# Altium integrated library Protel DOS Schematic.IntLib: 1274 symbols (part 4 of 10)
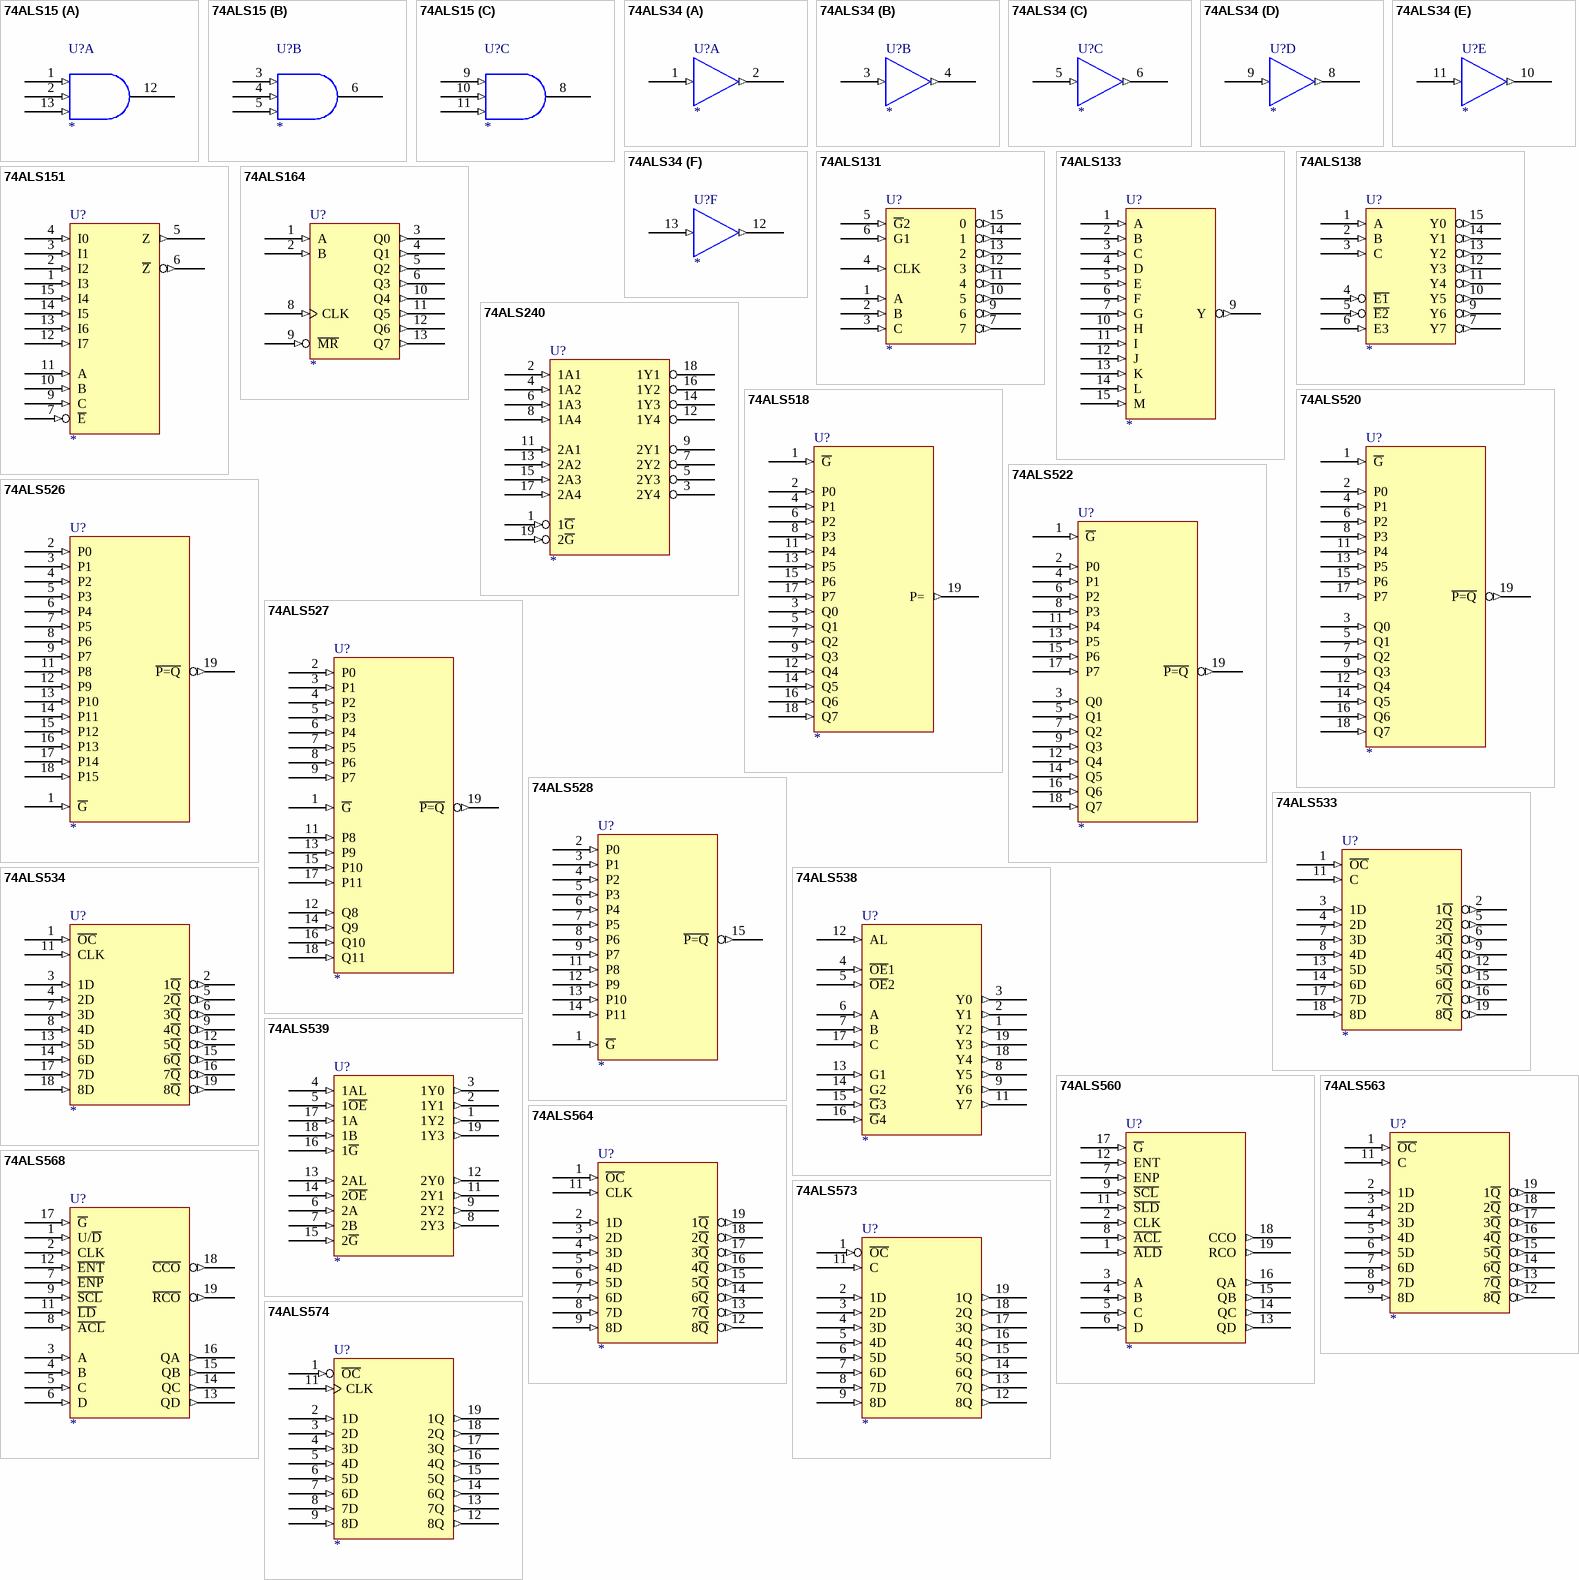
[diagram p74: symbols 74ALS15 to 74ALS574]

## 74ALS564
designator U?
footprint DIP-20
pins: 1 ~{OC} (in), 2 1D (in), 3 2D (in), 4 3D (in), 5 4D (in), 6 5D (in), 7 6D (in), 8 7D (in), 9 8D (in), 10 GND (power) hidden to GND, 11 CLK (in), 12 8~{Q} (out), 13 7~{Q} (out), 14 6~{Q} (out), 15 5~{Q} (out), 16 4~{Q} (out), 17 3~{Q} (out), 18 2~{Q} (out), 19 1~{Q} (out), 20 VCC (power) hidden to VCC
2 alternate drawings of the same symbol

## 74ALS568
designator U?
footprint DIP-20
pins: 1 U/~{D} (in), 2 CLK (in), 3 A (in), 4 B (in), 5 C (in), 6 D (in), 7 ~{ENP} (in), 8 ~{ACL} (in), 9 ~{SCL} (in), 10 GND (power) hidden to GND, 11 ~{LD} (in), 12 ~{ENT} (in), 13 QD (out), 14 QC (out), 15 QB (out), 16 QA (out), 17 ~{G} (in), 18 ~{CCO} (out), 19 ~{RCO} (out), 20 VCC (power) hidden to VCC
2 alternate drawings of the same symbol

## 74ALS573
designator U?
footprint DIP-20
footprint DIP20-O
pins: 1 ~{OC} (in), 2 1D (in), 3 2D (in), 4 3D (in), 5 4D (in), 6 5D (in), 7 6D (in), 8 7D (in), 9 8D (in), 10 GND (power) hidden to GND, 11 C (in), 12 8Q (out), 13 7Q (out), 14 6Q (out), 15 5Q (out), 16 4Q (out), 17 3Q (out), 18 2Q (out), 19 1Q (out), 20 VCC (power) hidden to VCC
2 alternate drawings of the same symbol

## 74ALS574
designator U?
footprint DIP-20
pins: 1 ~{OC} (in), 2 1D (in), 3 2D (in), 4 3D (in), 5 4D (in), 6 5D (in), 7 6D (in), 8 7D (in), 9 8D (in), 10 GND (power) hidden to GND, 11 CLK (in), 12 8Q (out), 13 7Q (out), 14 6Q (out), 15 5Q (out), 16 4Q (out), 17 3Q (out), 18 2Q (out), 19 1Q (out), 20 VCC (power) hidden to VCC
2 alternate drawings of the same symbol

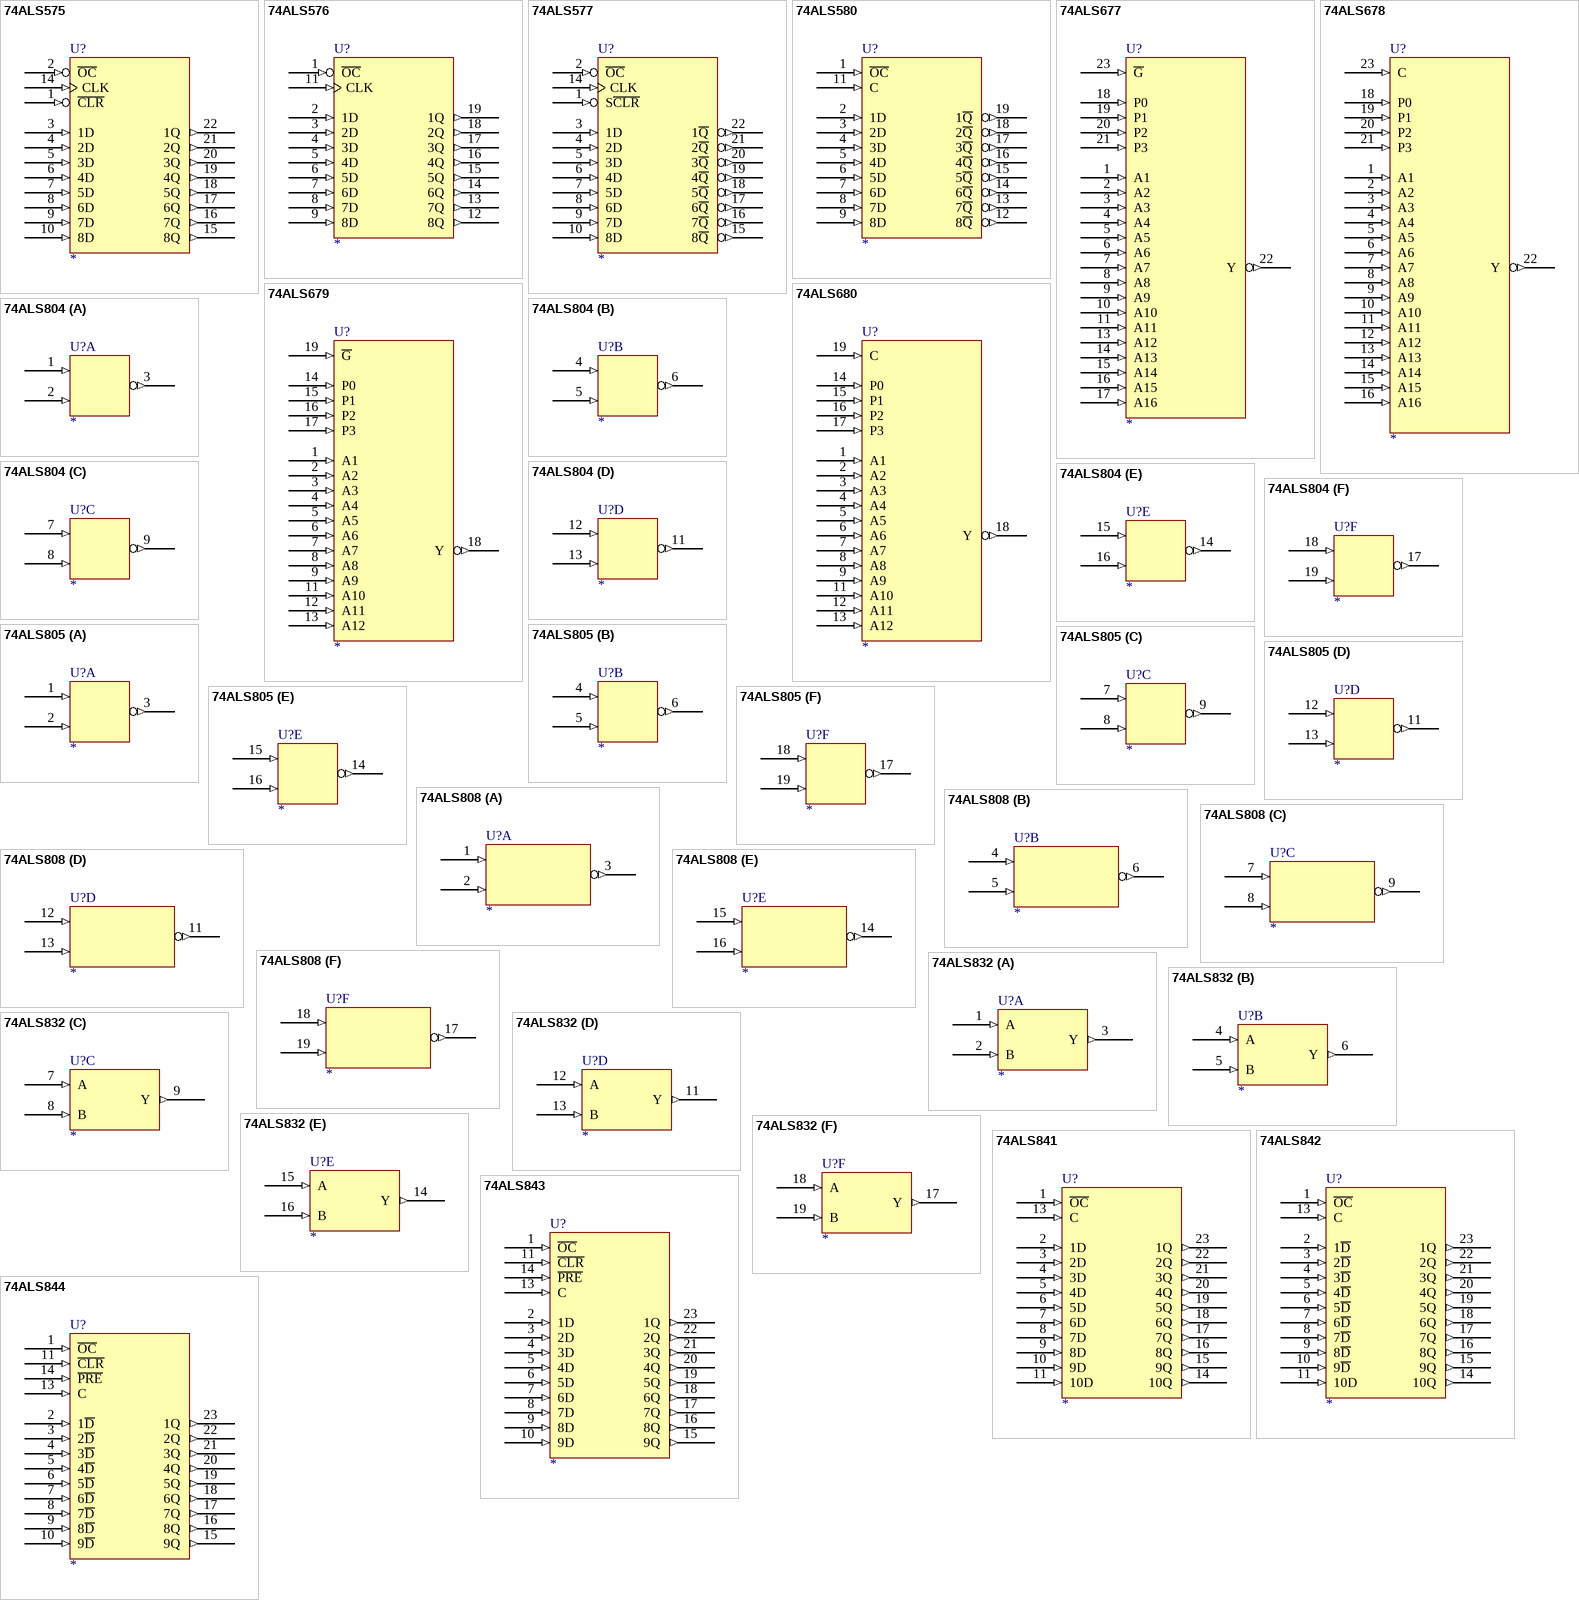
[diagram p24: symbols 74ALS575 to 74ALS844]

## 74ALS575
designator U?
footprint DIP-24
pins: 1 ~{CLR} (in), 2 ~{OC} (in), 3 1D (in), 4 2D (in), 5 3D (in), 6 4D (in), 7 5D (in), 8 6D (in), 9 7D (in), 10 8D (in), 12 GND (power) hidden to GND, 14 CLK (in), 15 8Q (out), 16 7Q (out), 17 6Q (out), 18 5Q (out), 19 4Q (out), 20 3Q (out), 21 2Q (out), 22 1Q (out), 24 VCC (power) hidden to VCC
2 alternate drawings of the same symbol

## 74ALS576
designator U?
footprint DIP-20
pins: 1 ~{OC} (in), 2 1D (in), 3 2D (in), 4 3D (in), 5 4D (in), 6 5D (in), 7 6D (in), 8 7D (in), 9 8D (in), 10 GND (power) hidden to GND, 11 CLK (in), 12 8Q (out), 13 7Q (out), 14 6Q (out), 15 5Q (out), 16 4Q (out), 17 3Q (out), 18 2Q (out), 19 1Q (out), 20 VCC (power) hidden to VCC
2 alternate drawings of the same symbol

## 74ALS577
designator U?
footprint DIP-24
pins: 1 S~{CLR} (in), 2 ~{OC} (in), 3 1D (in), 4 2D (in), 5 3D (in), 6 4D (in), 7 5D (in), 8 6D (in), 9 7D (in), 10 8D (in), 12 GND (power) hidden to GND, 14 CLK (in), 15 8~{Q} (out), 16 7~{Q} (out), 17 6~{Q} (out), 18 5~{Q} (out), 19 4~{Q} (out), 20 3~{Q} (out), 21 2~{Q} (out), 22 1~{Q} (out), 24 VCC (power) hidden to VCC
2 alternate drawings of the same symbol

## 74ALS580
designator U?
footprint DIP-20
pins: 1 ~{OC} (in), 2 1D (in), 3 2D (in), 4 3D (in), 5 4D (in), 6 5D (in), 7 6D (in), 8 7D (in), 9 8D (in), 10 GND (power) hidden to GND, 11 C (in), 12 8~{Q} (out), 13 7~{Q} (out), 14 6~{Q} (out), 15 5~{Q} (out), 16 4~{Q} (out), 17 3~{Q} (out), 18 2~{Q} (out), 19 1~{Q} (out), 20 VCC (power) hidden to VCC
2 alternate drawings of the same symbol

## 74ALS677
designator U?
footprint DIP-24
pins: 1 A1 (in), 2 A2 (in), 3 A3 (in), 4 A4 (in), 5 A5 (in), 6 A6 (in), 7 A7 (in), 8 A8 (in), 9 A9 (in), 10 A10 (in), 11 A11 (in), 12 GND (power) hidden to GND, 13 A12 (in), 14 A13 (in), 15 A14 (in), 16 A15 (in), 17 A16 (in), 18 P0 (in), 19 P1 (in), 20 P2 (in), 21 P3 (in), 22 Y (out), 23 ~{G} (in), 24 VCC (power) hidden to VCC
2 alternate drawings of the same symbol

## 74ALS678
designator U?
footprint DIP-24
pins: 1 A1 (in), 2 A2 (in), 3 A3 (in), 4 A4 (in), 5 A5 (in), 6 A6 (in), 7 A7 (in), 8 A8 (in), 9 A9 (in), 10 A10 (in), 11 A11 (in), 12 A12 (in), 12 GND (power) hidden to GND, 13 A13 (in), 14 A14 (in), 15 A15 (in), 16 A16 (in), 18 P0 (in), 19 P1 (in), 20 P2 (in), 21 P3 (in), 22 Y (out), 23 C (in), 24 VCC (power) hidden to VCC
2 alternate drawings of the same symbol

## 74ALS679
designator U?
footprint DIP-20
pins: 1 A1 (in), 2 A2 (in), 3 A3 (in), 4 A4 (in), 5 A5 (in), 6 A6 (in), 7 A7 (in), 8 A8 (in), 9 A9 (in), 10 GND (power) hidden to GND, 11 A10 (in), 12 A11 (in), 13 A12 (in), 14 P0 (in), 15 P1 (in), 16 P2 (in), 17 P3 (in), 18 Y (out), 19 ~{G} (in), 20 VCC (power) hidden to VCC
2 alternate drawings of the same symbol

## 74ALS680
designator U?
footprint DIP-20
pins: 1 A1 (in), 2 A2 (in), 3 A3 (in), 4 A4 (in), 5 A5 (in), 6 A6 (in), 7 A7 (in), 8 A8 (in), 9 A9 (in), 10 GND (power) hidden to GND, 11 A10 (in), 12 A11 (in), 13 A12 (in), 14 P0 (in), 15 P1 (in), 16 P2 (in), 17 P3 (in), 18 Y (out), 19 C (in), 20 VCC (power) hidden to VCC
2 alternate drawings of the same symbol

## 74ALS804
designator U?
footprint DIP-20
part A pins: 1 (in), 2 (in), 3 (out), 10 GND (power) hidden to GND, 20 VCC (power) hidden to VCC
part B pins: 4 (in), 5 (in), 6 (out), 10 GND (power) hidden to GND, 20 VCC (power) hidden to VCC
part C pins: 7 (in), 8 (in), 9 (out), 10 GND (power) hidden to GND, 20 VCC (power) hidden to VCC
part D pins: 10 GND (power) hidden to GND, 11 (out), 12 (in), 13 (in), 20 VCC (power) hidden to VCC
part E pins: 10 GND (power) hidden to GND, 14 (out), 15 (in), 16 (in), 20 VCC (power) hidden to VCC
part F pins: 10 GND (power) hidden to GND, 17 (out), 18 (in), 19 (in), 20 VCC (power) hidden to VCC
2 alternate drawings of the same symbol

## 74ALS805
designator U?
footprint DIP-20
part A pins: 1 (in), 2 (in), 3 (out), 10 GND (power) hidden to GND, 20 VCC (power) hidden to VCC
part B pins: 4 (in), 5 (in), 6 (out), 10 GND (power) hidden to GND, 20 VCC (power) hidden to VCC
part C pins: 7 (in), 8 (in), 9 (out), 10 GND (power) hidden to GND, 20 VCC (power) hidden to VCC
part D pins: 10 GND (power) hidden to GND, 11 (out), 12 (in), 13 (in), 20 VCC (power) hidden to VCC
part E pins: 10 GND (power) hidden to GND, 14 (out), 15 (in), 16 (in), 20 VCC (power) hidden to VCC
part F pins: 10 GND (power) hidden to GND, 17 (out), 18 (in), 19 (in), 20 VCC (power) hidden to VCC
2 alternate drawings of the same symbol

## 74ALS808
designator U?
footprint DIP-20
part A pins: 1 (in), 2 (in), 3 (out), 10 GND (power) hidden to GND, 20 VCC (power) hidden to VCC
part B pins: 4 (in), 5 (in), 6 (out), 10 GND (power) hidden to GND, 20 VCC (power) hidden to VCC
part C pins: 7 (in), 8 (in), 9 (out), 10 GND (power) hidden to GND, 20 VCC (power) hidden to VCC
part D pins: 10 GND (power) hidden to GND, 11 (out), 12 (in), 13 (in), 20 VCC (power) hidden to VCC
part E pins: 10 GND (power) hidden to GND, 14 (out), 15 (in), 16 (in), 20 VCC (power) hidden to VCC
part F pins: 10 GND (power) hidden to GND, 17 (out), 18 (in), 19 (in), 20 VCC (power) hidden to VCC
2 alternate drawings of the same symbol

## 74ALS832
designator U?
footprint DIP-20
part A pins: 1 A (in), 2 B (in), 3 Y (out), 10 GND (power) hidden to GND, 20 VCC (power) hidden to VCC
part B pins: 4 A (in), 5 B (in), 6 Y (out), 10 GND (power) hidden to GND, 20 VCC (power) hidden to VCC
part C pins: 7 A (in), 8 B (in), 9 Y (out), 10 GND (power) hidden to GND, 20 VCC (power) hidden to VCC
part D pins: 10 GND (power) hidden to GND, 11 Y (out), 12 A (in), 13 B (in), 20 VCC (power) hidden to VCC
part E pins: 10 GND (power) hidden to GND, 14 Y (out), 15 A (in), 16 B (in), 20 VCC (power) hidden to VCC
part F pins: 10 GND (power) hidden to GND, 17 Y (out), 18 A (in), 19 B (in), 20 VCC (power) hidden to VCC
2 alternate drawings of the same symbol

## 74ALS841
designator U?
footprint DIP-24
pins: 1 ~{OC} (in), 2 1D (in), 3 2D (in), 4 3D (in), 5 4D (in), 6 5D (in), 7 6D (in), 8 7D (in), 9 8D (in), 10 9D (in), 11 10D (in), 12 GND (power) hidden to GND, 13 C (in), 14 10Q (out), 15 9Q (out), 16 8Q (out), 17 7Q (out), 18 6Q (out), 19 5Q (out), 20 4Q (out), 21 3Q (out), 22 2Q (out), 23 1Q (out), 24 VCC (power) hidden to VCC
2 alternate drawings of the same symbol

## 74ALS842
designator U?
footprint DIP-24
pins: 1 ~{OC} (in), 2 1~{D} (in), 3 2~{D} (in), 4 3~{D} (in), 5 4~{D} (in), 6 5~{D} (in), 7 6~{D} (in), 8 7~{D} (in), 9 8~{D} (in), 10 9~{D} (in), 11 10D (in), 12 GND (power) hidden to GND, 13 C (in), 14 10Q (out), 15 9Q (out), 16 8Q (out), 17 7Q (out), 18 6Q (out), 19 5Q (out), 20 4Q (out), 21 3Q (out), 22 2Q (out), 23 1Q (out), 24 VCC (power) hidden to VCC
2 alternate drawings of the same symbol

## 74ALS843
designator U?
footprint DIP-24
pins: 1 ~{OC} (in), 2 1D (in), 3 2D (in), 4 3D (in), 5 4D (in), 6 5D (in), 7 6D (in), 8 7D (in), 9 8D (in), 10 9D (in), 11 ~{CLR} (in), 12 GND (power) hidden to GND, 13 C (in), 14 ~{PRE} (in), 15 9Q (out), 16 8Q (out), 17 7Q (out), 18 6Q (out), 19 5Q (out), 20 4Q (out), 21 3Q (out), 22 2Q (out), 23 1Q (out), 24 VCC (power) hidden to VCC
2 alternate drawings of the same symbol

## 74ALS844
designator U?
footprint DIP-24
pins: 1 ~{OC} (in), 2 1~{D} (in), 3 2~{D} (in), 4 3~{D} (in), 5 4~{D} (in), 6 5~{D} (in), 7 6~{D} (in), 8 7~{D} (in), 9 8~{D} (in), 10 9~{D} (in), 11 ~{CLR} (in), 12 GND (power) hidden to GND, 13 C (in), 14 ~{PRE} (in), 15 9Q (out), 16 8Q (out), 17 7Q (out), 18 6Q (out), 19 5Q (out), 20 4Q (out), 21 3Q (out), 22 2Q (out), 23 1Q (out), 24 VCC (power) hidden to VCC
2 alternate drawings of the same symbol

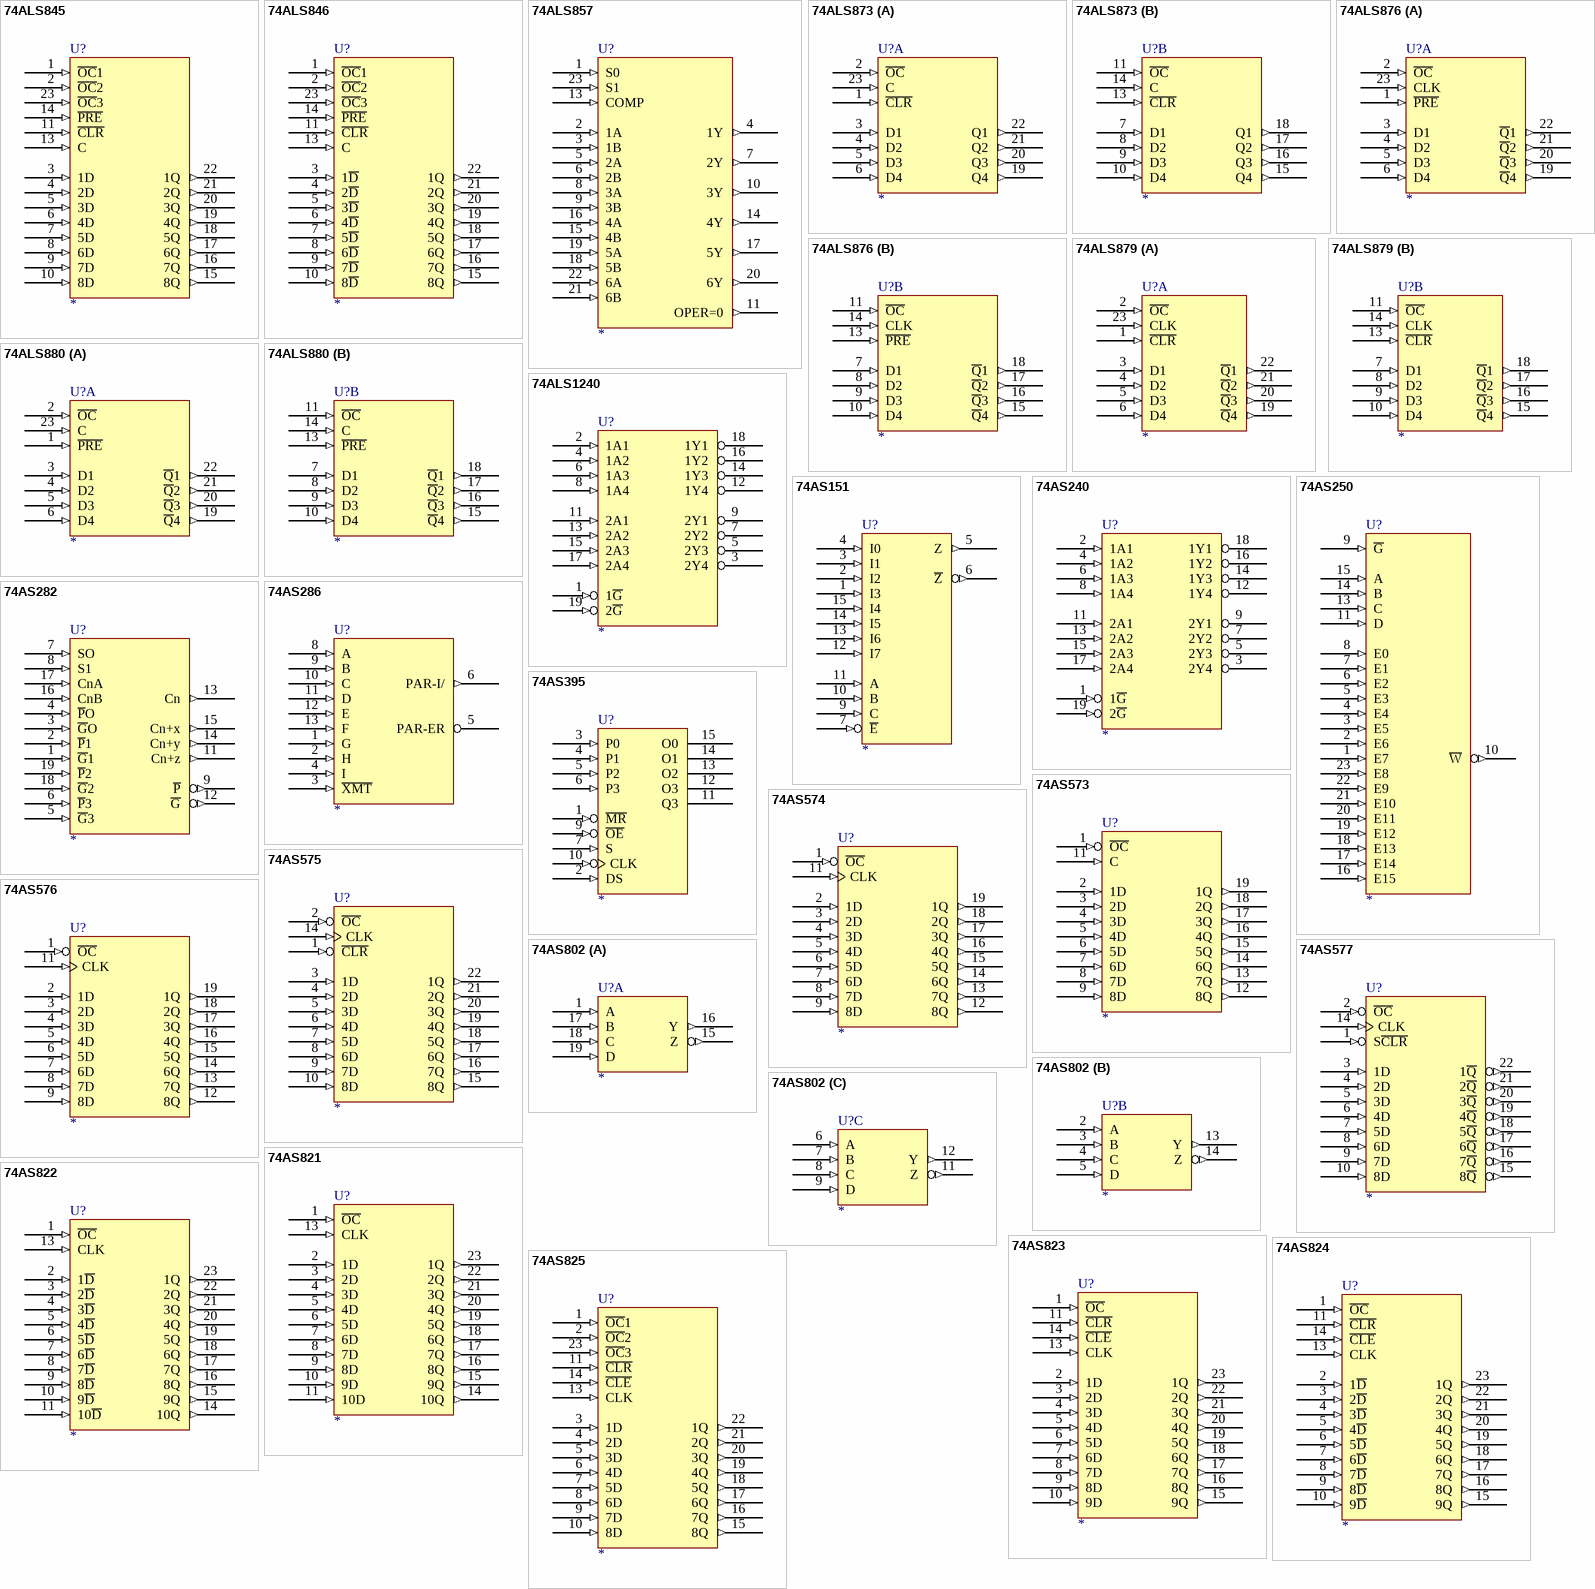
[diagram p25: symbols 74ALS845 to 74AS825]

## 74ALS845
designator U?
footprint DIP-24
pins: 1 ~{OC}1 (in), 2 ~{OC}2 (in), 3 1D (in), 4 2D (in), 5 3D (in), 6 4D (in), 7 5D (in), 8 6D (in), 9 7D (in), 10 8D (in), 11 ~{CLR} (in), 12 GND (power) hidden to GND, 13 C (in), 14 ~{PRE} (in), 15 8Q (out), 16 7Q (out), 17 6Q (out), 18 5Q (out), 19 4Q (out), 20 3Q (out), 21 2Q (out), 22 1Q (out), 23 ~{OC}3 (in), 24 VCC (power) hidden to VCC
2 alternate drawings of the same symbol

## 74ALS846
designator U?
footprint DIP-24
pins: 1 ~{OC}1 (in), 2 ~{OC}2 (in), 3 1~{D} (in), 4 2~{D} (in), 5 3~{D} (in), 6 4~{D} (in), 7 5~{D} (in), 8 6~{D} (in), 9 7~{D} (in), 10 8~{D} (in), 11 ~{CLR} (in), 12 GND (power) hidden to GND, 13 C (in), 14 ~{PRE} (in), 15 8Q (out), 16 7Q (out), 17 6Q (out), 18 5Q (out), 19 4Q (out), 20 3Q (out), 21 2Q (out), 22 1Q (out), 23 ~{OC}3 (in), 24 VCC (power) hidden to VCC
2 alternate drawings of the same symbol

## 74ALS857
designator U?
footprint DIP-24
pins: 1 S0 (in), 2 1A (in), 3 1B (in), 4 1Y (out), 5 2A (in), 6 2B (in), 7 2Y (out), 8 3A (in), 9 3B (in), 10 3Y (out), 11 OPER=0 (out), 12 GND (power) hidden to GND, 13 COMP (in), 14 4Y (out), 15 4B (in), 16 4A (in), 17 5Y (out), 18 5B (in), 19 5A (in), 20 6Y (out), 21 6B (in), 22 6A (in), 23 S1 (in), 24 VCC (power) hidden to VCC
2 alternate drawings of the same symbol

## 74ALS873
designator U?
footprint DIP-24
part A pins: 1 ~{CLR} (in), 2 ~{OC} (in), 3 D1 (in), 4 D2 (in), 5 D3 (in), 6 D4 (in), 12 GND (power) hidden to GND, 19 Q4 (out), 20 Q3 (out), 21 Q2 (out), 22 Q1 (out), 23 C (in), 24 VCC (power) hidden to VCC
part B pins: 7 D1 (in), 8 D2 (in), 9 D3 (in), 10 D4 (in), 11 ~{OC} (in), 12 GND (power) hidden to GND, 13 ~{CLR} (in), 14 C (in), 15 Q4 (out), 16 Q3 (out), 17 Q2 (out), 18 Q1 (out), 24 VCC (power) hidden to VCC
2 alternate drawings of the same symbol

## 74ALS876
designator U?
footprint DIP-24
part A pins: 1 ~{PRE} (in), 2 ~{OC} (in), 3 D1 (in), 4 D2 (in), 5 D3 (in), 6 D4 (in), 12 GND (power) hidden to GND, 19 ~{Q}4 (out), 20 ~{Q}3 (out), 21 ~{Q}2 (out), 22 ~{Q}1 (out), 23 CLK (in), 24 VCC (power) hidden to VCC
part B pins: 7 D1 (in), 8 D2 (in), 9 D3 (in), 10 D4 (in), 11 ~{OC} (in), 12 GND (power) hidden to GND, 13 ~{PRE} (in), 14 CLK (in), 15 ~{Q}4 (out), 16 ~{Q}3 (out), 17 ~{Q}2 (out), 18 ~{Q}1 (out), 24 VCC (power) hidden to VCC
2 alternate drawings of the same symbol

## 74ALS879
designator U?
footprint DIP-24
part A pins: 1 ~{CLR} (in), 2 ~{OC} (in), 3 D1 (in), 4 D2 (in), 5 D3 (in), 6 D4 (in), 12 GND (power) hidden to GND, 19 ~{Q}4 (out), 20 ~{Q}3 (out), 21 ~{Q}2 (out), 22 ~{Q}1 (out), 23 CLK (in), 24 VCC (power) hidden to VCC
part B pins: 7 D1 (in), 8 D2 (in), 9 D3 (in), 10 D4 (in), 11 ~{OC} (in), 12 GND (power) hidden to GND, 13 ~{CLR} (in), 14 CLK (in), 15 ~{Q}4 (out), 16 ~{Q}3 (out), 17 ~{Q}2 (out), 18 ~{Q}1 (out), 24 VCC (power) hidden to VCC
2 alternate drawings of the same symbol

## 74ALS880
designator U?
footprint DIP-24
part A pins: 1 ~{PRE} (in), 2 ~{OC} (in), 3 D1 (in), 4 D2 (in), 5 D3 (in), 6 D4 (in), 12 GND (power) hidden to GND, 19 ~{Q}4 (out), 20 ~{Q}3 (out), 21 ~{Q}2 (out), 22 ~{Q}1 (out), 23 C (in), 24 VCC (power) hidden to VCC
part B pins: 7 D1 (in), 8 D2 (in), 9 D3 (in), 10 D4 (in), 11 ~{OC} (in), 12 GND (power) hidden to GND, 13 ~{PRE} (in), 14 C (in), 15 ~{Q}4 (out), 16 ~{Q}3 (out), 17 ~{Q}2 (out), 18 ~{Q}1 (out), 24 VCC (power) hidden to VCC
2 alternate drawings of the same symbol

## 74ALS1240
designator U?
footprint DIP-20
pins: 1 1~{G} (in), 2 1A1 (in), 3 2Y4 (hiz), 4 1A2 (in), 5 2Y3 (hiz), 6 1A3 (in), 7 2Y2 (hiz), 8 1A4 (in), 9 2Y1 (hiz), 10 GND (power) hidden to GND, 11 2A1 (in), 12 1Y4 (hiz), 13 2A2 (in), 14 1Y3 (hiz), 15 2A3 (in), 16 1Y2 (hiz), 17 2A4 (in), 18 1Y1 (hiz), 19 2~{G} (in), 20 VCC (power) hidden to VCC
2 alternate drawings of the same symbol

## 74AS151
designator U?
footprint DIP-16
pins: 1 I3 (in), 2 I2 (in), 3 I1 (in), 4 I0 (in), 5 Z (out), 6 ~{Z} (out), 7 ~{E} (in), 8 GND (power) hidden to GND, 9 C (in), 10 B (in), 11 A (in), 12 I7 (in), 13 I6 (in), 14 I5 (in), 15 I4 (in), 16 VCC (power) hidden to VCC
2 alternate drawings of the same symbol

## 74AS240
designator U?
footprint DIP-20
pins: 1 1~{G} (in), 2 1A1 (in), 3 2Y4 (hiz), 4 1A2 (in), 5 2Y3 (hiz), 6 1A3 (in), 7 2Y2 (hiz), 8 1A4 (in), 9 2Y1 (hiz), 10 GND (power) hidden to GND, 11 2A1 (in), 12 1Y4 (hiz), 13 2A2 (in), 14 1Y3 (hiz), 15 2A3 (in), 16 1Y2 (hiz), 17 2A4 (in), 18 1Y1 (hiz), 19 2~{G} (in), 20 VCC (power) hidden to VCC
2 alternate drawings of the same symbol

## 74AS250
designator U?
footprint DIP-24
pins: 1 E7 (in), 2 E6 (in), 3 E5 (in), 4 E4 (in), 5 E3 (in), 6 E2 (in), 7 E1 (in), 8 E0 (in), 9 ~{G} (in), 10 ~{W} (out), 11 D (in), 12 GND (power) hidden to GND, 13 C (in), 14 B (in), 15 A (in), 16 E15 (in), 17 E14 (in), 18 E13 (in), 19 E12 (in), 20 E11 (in), 21 E10 (in), 22 E9 (in), 23 E8 (in), 24 VCC (power) hidden to VCC
2 alternate drawings of the same symbol

## 74AS282
designator U?
footprint DIP-20
pins: 1 ~{G}1 (in), 2 ~{P}1 (in), 3 ~{G}O (in), 4 ~{P}O (in), 5 ~{G}3 (in), 6 ~{P}3 (in), 7 SO (in), 8 S1 (in), 9 ~{P} (out), 10 GND (power) hidden to GND, 11 Cn+z (out), 12 ~{G} (out), 13 Cn (out), 14 Cn+y (out), 15 Cn+x (out), 16 CnB (in), 17 CnA (in), 18 ~{G}2 (in), 19 ~{P}2 (in), 20 VCC (power) hidden to VCC
2 alternate drawings of the same symbol

## 74AS286
designator U?
footprint DIP-14
pins: 1 G (in), 2 H (in), 3 ~{XMT} (in), 4 I (in), 5 PAR-ER, 6 PAR-I/ (out), 7 GND (power) hidden to GND, 8 A (in), 9 B (in), 10 C (in), 11 D (in), 12 E (in), 13 F (in), 14 VCC (power) hidden to VCC
2 alternate drawings of the same symbol

## 74AS395
designator U?
footprint DIP-16
pins: 1 ~{MR} (in), 2 DS (in), 3 P0 (in), 4 P1 (in), 5 P2 (in), 6 P3 (in), 7 S (in), 8 GND (power) hidden to GND, 9 ~{OE} (in), 10 CLK (in), 11 Q3 (hiz), 12 O3 (hiz), 13 O2 (hiz), 14 O1 (hiz), 15 O0 (hiz), 16 VCC (power) hidden to VCC
2 alternate drawings of the same symbol

## 74AS573
designator U?
footprint DIP-20
pins: 1 ~{OC} (in), 2 1D (in), 3 2D (in), 4 3D (in), 5 4D (in), 6 5D (in), 7 6D (in), 8 7D (in), 9 8D (in), 10 GND (power) hidden to GND, 11 C (in), 12 8Q (out), 13 7Q (out), 14 6Q (out), 15 5Q (out), 16 4Q (out), 17 3Q (out), 18 2Q (out), 19 1Q (out), 20 VCC (power) hidden to VCC
2 alternate drawings of the same symbol

## 74AS574
designator U?
footprint DIP-20
pins: 1 ~{OC} (in), 2 1D (in), 3 2D (in), 4 3D (in), 5 4D (in), 6 5D (in), 7 6D (in), 8 7D (in), 9 8D (in), 10 GND (power) hidden to GND, 11 CLK (in), 12 8Q (out), 13 7Q (out), 14 6Q (out), 15 5Q (out), 16 4Q (out), 17 3Q (out), 18 2Q (out), 19 1Q (out), 20 VCC (power) hidden to VCC
2 alternate drawings of the same symbol

## 74AS575
designator U?
footprint DIP-24
pins: 1 ~{CLR} (in), 2 ~{OC} (in), 3 1D (in), 4 2D (in), 5 3D (in), 6 4D (in), 7 5D (in), 8 6D (in), 9 7D (in), 10 8D (in), 12 GND (power) hidden to GND, 14 CLK (in), 15 8Q (out), 16 7Q (out), 17 6Q (out), 18 5Q (out), 19 4Q (out), 20 3Q (out), 21 2Q (out), 22 1Q (out), 24 VCC (power) hidden to VCC
2 alternate drawings of the same symbol

## 74AS576
designator U?
footprint DIP-20
pins: 1 ~{OC} (in), 2 1D (in), 3 2D (in), 4 3D (in), 5 4D (in), 6 5D (in), 7 6D (in), 8 7D (in), 9 8D (in), 10 GND (power) hidden to GND, 11 CLK (in), 12 8Q (out), 13 7Q (out), 14 6Q (out), 15 5Q (out), 16 4Q (out), 17 3Q (out), 18 2Q (out), 19 1Q (out), 20 VCC (power) hidden to VCC
2 alternate drawings of the same symbol

## 74AS577
designator U?
footprint DIP-24
pins: 1 S~{CLR} (in), 2 ~{OC} (in), 3 1D (in), 4 2D (in), 5 3D (in), 6 4D (in), 7 5D (in), 8 6D (in), 9 7D (in), 10 8D (in), 12 GND (power) hidden to GND, 14 CLK (in), 15 8~{Q} (out), 16 7~{Q} (out), 17 6~{Q} (out), 18 5~{Q} (out), 19 4~{Q} (out), 20 3~{Q} (out), 21 2~{Q} (out), 22 1~{Q} (out), 24 VCC (power) hidden to VCC
2 alternate drawings of the same symbol

## 74AS802
designator U?
footprint DIP-20
part A pins: 1 A (in), 10 GND (power) hidden to GND, 15 Z (out), 16 Y (out), 17 B (in), 18 C (in), 19 D (in), 20 VCC (power) hidden to VCC
part B pins: 2 A (in), 3 B (in), 4 C (in), 5 D (in), 10 GND (power) hidden to GND, 13 Y (out), 14 Z (out), 20 VCC (power) hidden to VCC
part C pins: 6 A (in), 7 B (in), 8 C (in), 9 D (in), 10 GND (power) hidden to GND, 11 Z (out), 12 Y (out), 20 VCC (power) hidden to VCC
2 alternate drawings of the same symbol

## 74AS821
designator U?
footprint DIP-24
pins: 1 ~{OC} (in), 2 1D (in), 3 2D (in), 4 3D (in), 5 4D (in), 6 5D (in), 7 6D (in), 8 7D (in), 9 8D (in), 10 9D (in), 11 10D (in), 12 GND (power) hidden to GND, 13 CLK (in), 14 10Q (out), 15 9Q (out), 16 8Q (out), 17 7Q (out), 18 6Q (out), 19 5Q (out), 20 4Q (out), 21 3Q (out), 22 2Q (out), 23 1Q (out), 24 VCC (power) hidden to VCC
2 alternate drawings of the same symbol

## 74AS822
designator U?
footprint DIP-24
pins: 1 ~{OC} (in), 2 1~{D} (in), 3 2~{D} (in), 4 3~{D} (in), 5 4~{D} (in), 6 5~{D} (in), 7 6~{D} (in), 8 7~{D} (in), 9 8~{D} (in), 10 9~{D} (in), 11 10~{D} (in), 12 GND (power) hidden to GND, 13 CLK (in), 14 10Q (out), 15 9Q (out), 16 8Q (out), 17 7Q (out), 18 6Q (out), 19 5Q (out), 20 4Q (out), 21 3Q (out), 22 2Q (out), 23 1Q (out), 24 VCC (power) hidden to VCC
2 alternate drawings of the same symbol

## 74AS823
designator U?
footprint DIP-24
pins: 1 ~{OC} (in), 2 1D (in), 3 2D (in), 4 3D (in), 5 4D (in), 6 5D (in), 7 6D (in), 8 7D (in), 9 8D (in), 10 9D (in), 11 ~{CLR} (in), 12 GND (power) hidden to GND, 13 CLK (in), 14 ~{CLE} (in), 15 9Q (out), 16 8Q (out), 17 7Q (out), 18 6Q (out), 19 5Q (out), 20 4Q (out), 21 3Q (out), 22 2Q (out), 23 1Q (out), 24 VCC (power) hidden to VCC
2 alternate drawings of the same symbol

## 74AS824
designator U?
footprint DIP-24
pins: 1 ~{OC} (in), 2 1~{D} (in), 3 2~{D} (in), 4 3~{D} (in), 5 4~{D} (in), 6 5~{D} (in), 7 6~{D} (in), 8 7~{D} (in), 9 8~{D} (in), 10 9~{D} (in), 11 ~{CLR} (in), 12 GND (power) hidden to GND, 13 CLK (in), 14 ~{CLE} (in), 15 9Q (out), 16 8Q (out), 17 7Q (out), 18 6Q (out), 19 5Q (out), 20 4Q (out), 21 3Q (out), 22 2Q (out), 23 1Q (out), 24 VCC (power) hidden to VCC
2 alternate drawings of the same symbol

## 74AS825
designator U?
footprint DIP-24
pins: 1 ~{OC}1 (in), 2 ~{OC}2 (in), 3 1D (in), 4 2D (in), 5 3D (in), 6 4D (in), 7 5D (in), 8 6D (in), 9 7D (in), 10 8D (in), 11 ~{CLR} (in), 12 GND (power) hidden to GND, 13 CLK (in), 14 ~{CLE} (in), 15 8Q (out), 16 7Q (out), 17 6Q (out), 18 5Q (out), 19 4Q (out), 20 3Q (out), 21 2Q (out), 22 1Q (out), 23 ~{OC}3 (in), 24 VCC (power) hidden to VCC
2 alternate drawings of the same symbol

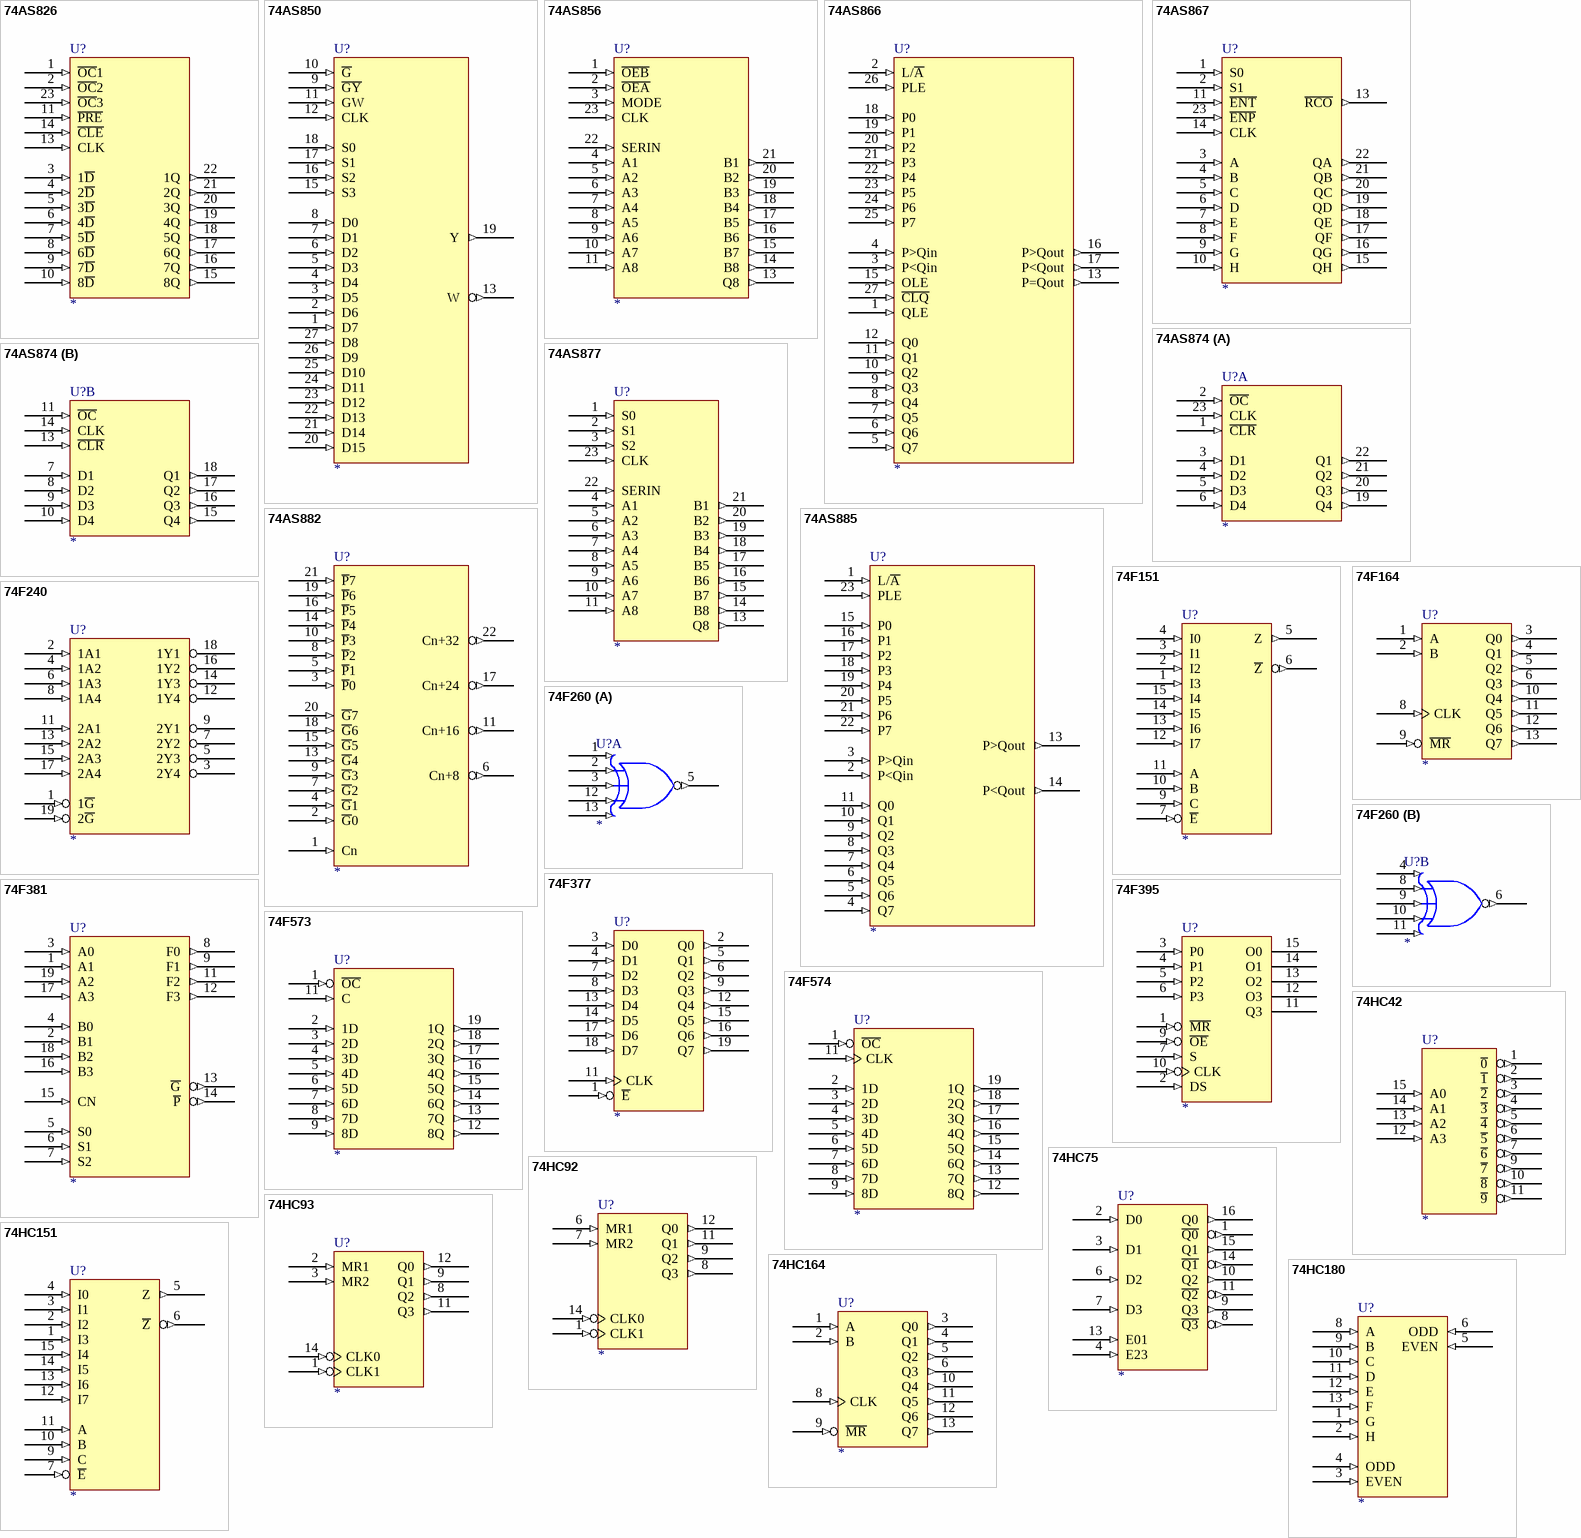
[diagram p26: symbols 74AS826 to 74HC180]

## 74AS826
designator U?
footprint DIP-24
pins: 1 ~{OC}1 (in), 2 ~{OC}2 (in), 3 1~{D} (in), 4 2~{D} (in), 5 3~{D} (in), 6 4~{D} (in), 7 5~{D} (in), 8 6~{D} (in), 9 7~{D} (in), 10 8~{D} (in), 11 ~{PRE} (in), 12 GND (power) hidden to GND, 13 CLK (in), 14 ~{CLE} (in), 15 8Q (out), 16 7Q (out), 17 6Q (out), 18 5Q (out), 19 4Q (out), 20 3Q (out), 21 2Q (out), 22 1Q (out), 23 ~{OC}3 (in), 24 VCC (power) hidden to VCC
2 alternate drawings of the same symbol

## 74AS850
designator U?
footprint DIP-28
pins: 1 D7 (in), 2 D6 (in), 3 D5 (in), 4 D4 (in), 5 D3 (in), 6 D2 (in), 7 D1 (in), 8 D0 (in), 9 ~{GY} (in), 10 ~{G} (in), 11 GW (in), 12 CLK (in), 13 W (out), 14 GND (power) hidden to GND, 15 S3 (in), 16 S2 (in), 17 S1 (in), 18 S0 (in), 19 Y (out), 20 D15 (in), 21 D14 (in), 22 D13 (in), 23 D12 (in), 24 D11 (in), 25 D10 (in), 26 D9 (in), 27 D8 (in), 28 VCC (power) hidden to VCC
2 alternate drawings of the same symbol

## 74AS856
designator U?
footprint DIP-24
pins: 1 ~{OEB} (in), 2 ~{OEA} (in), 3 MODE (in), 4 A1 (in), 5 A2 (in), 6 A3 (in), 7 A4 (in), 8 A5 (in), 9 A6 (in), 10 A7 (in), 11 A8 (in), 12 GND (power) hidden to GND, 13 Q8 (out), 14 B8 (out), 15 B7 (out), 16 B6 (out), 17 B5 (out), 18 B4 (out), 19 B3 (out), 20 B2 (out), 21 B1 (out), 22 SERIN (in), 23 CLK (in), 24 VCC (power) hidden to VCC
2 alternate drawings of the same symbol

## 74AS866
designator U?
footprint DIP-28
pins: 1 QLE (in), 2 L/~{A} (in), 3 P<Qin (in), 4 P>Qin (in), 5 Q7 (in), 6 Q6 (in), 7 Q5 (in), 8 Q4 (in), 9 Q3 (in), 10 Q2 (in), 11 Q1 (in), 12 Q0 (in), 13 P=Qout (out), 14 GND (power) hidden to GND, 15 OLE (in), 16 P>Qout (out), 17 P<Qout (out), 18 P0 (in), 19 P1 (in), 20 P2 (in), 21 P3 (in), 22 P4 (in), 23 P5 (in), 24 P6 (in), 25 P7 (in), 26 PLE (in), 27 ~{CLQ} (in), 28 VCC (power) hidden to VCC
2 alternate drawings of the same symbol

## 74AS867
designator U?
footprint DIP-24
pins: 1 S0 (in), 2 S1 (in), 3 A (in), 4 B (in), 5 C (in), 6 D (in), 7 E (in), 8 F (in), 9 G (in), 10 H (in), 11 ~{ENT} (in), 12 GND (power) hidden to GND, 13 ~{RCO} (out), 14 CLK (in), 15 QH (out), 16 QG (out), 17 QF (out), 18 QE (out), 19 QD (out), 20 QC (out), 21 QB (out), 22 QA (out), 23 ~{ENP} (in), 24 VCC (power) hidden to VCC
2 alternate drawings of the same symbol

## 74AS874
designator U?
footprint DIP-24
part A pins: 1 ~{CLR} (in), 2 ~{OC} (in), 3 D1 (in), 4 D2 (in), 5 D3 (in), 6 D4 (in), 12 GND (power) hidden to GND, 19 Q4 (out), 20 Q3 (out), 21 Q2 (out), 22 Q1 (out), 23 CLK (in), 24 VCC (power) hidden to VCC
part B pins: 7 D1 (in), 8 D2 (in), 9 D3 (in), 10 D4 (in), 11 ~{OC} (in), 12 GND (power) hidden to GND, 13 ~{CLR} (in), 14 CLK (in), 15 Q4 (out), 16 Q3 (out), 17 Q2 (out), 18 Q1 (out), 24 VCC (power) hidden to VCC
2 alternate drawings of the same symbol

## 74AS877
designator U?
footprint DIP-24
pins: 1 S0 (in), 2 S1 (in), 3 S2 (in), 4 A1 (in), 5 A2 (in), 6 A3 (in), 7 A4 (in), 8 A5 (in), 9 A6 (in), 10 A7 (in), 11 A8 (in), 12 GND (power) hidden to GND, 13 Q8 (out), 14 B8 (out), 15 B7 (out), 16 B6 (out), 17 B5 (out), 18 B4 (out), 19 B3 (out), 20 B2 (out), 21 B1 (out), 22 SERIN (in), 23 CLK (in), 24 VCC (power) hidden to VCC
2 alternate drawings of the same symbol

## 74AS882
designator U?
footprint DIP-24
pins: 1 Cn (in), 2 ~{G}0 (in), 3 ~{P}0 (in), 4 ~{G}1 (in), 5 ~{P}1 (in), 6 Cn+8 (out), 7 ~{G}2 (in), 8 ~{P}2 (in), 9 ~{G}3 (in), 10 ~{P}3 (in), 11 Cn+16 (out), 12 GND (power) hidden to GND, 13 ~{G}4 (in), 14 ~{P}4 (in), 15 ~{G}5 (in), 16 ~{P}5 (in), 17 Cn+24 (out), 18 ~{G}6 (in), 19 ~{P}6 (in), 20 ~{G}7 (in), 21 ~{P}7 (in), 22 Cn+32 (out), 24 VCC (power) hidden to VCC
2 alternate drawings of the same symbol

## 74AS885
designator U?
footprint DIP-24
pins: 1 L/~{A} (in), 2 P<Qin (in), 3 P>Qin (in), 4 Q7 (in), 5 Q6 (in), 6 Q5 (in), 7 Q4 (in), 8 Q3 (in), 9 Q2 (in), 10 Q1 (in), 11 Q0 (in), 12 GND (power) hidden to GND, 13 P>Qout (out), 14 P<Qout (out), 15 P0 (in), 16 P1 (in), 17 P2 (in), 18 P3 (in), 19 P4 (in), 20 P5 (in), 21 P6 (in), 22 P7 (in), 23 PLE (in), 24 VCC (power) hidden to VCC
2 alternate drawings of the same symbol

## 74F151
designator U?
footprint DIP-16
pins: 1 I3 (in), 2 I2 (in), 3 I1 (in), 4 I0 (in), 5 Z (out), 6 ~{Z} (out), 7 ~{E} (in), 8 GND (power) hidden to GND, 9 C (in), 10 B (in), 11 A (in), 12 I7 (in), 13 I6 (in), 14 I5 (in), 15 I4 (in), 16 VCC (power) hidden to VCC
2 alternate drawings of the same symbol

## 74F164
designator U?
footprint DIP-14
pins: 1 A (in), 2 B (in), 3 Q0 (out), 4 Q1 (out), 5 Q2 (out), 6 Q3 (out), 7 GND (power) hidden to GND, 8 CLK (in), 9 ~{MR} (in), 10 Q4 (out), 11 Q5 (out), 12 Q6 (out), 13 Q7 (out), 14 VCC (power) hidden to VCC
2 alternate drawings of the same symbol

## 74F240
designator U?
footprint DIP-20
pins: 1 1~{G} (in), 2 1A1 (in), 3 2Y4 (hiz), 4 1A2 (in), 5 2Y3 (hiz), 6 1A3 (in), 7 2Y2 (hiz), 8 1A4 (in), 9 2Y1 (hiz), 10 GND (power) hidden to GND, 11 2A1 (in), 12 1Y4 (hiz), 13 2A2 (in), 14 1Y3 (hiz), 15 2A3 (in), 16 1Y2 (hiz), 17 2A4 (in), 18 1Y1 (hiz), 19 2~{G} (in), 20 VCC (power) hidden to VCC
2 alternate drawings of the same symbol

## 74F260
designator U?
footprint DIP-14
part A pins: 1 (in), 2 (in), 3 (in), 5 (out), 7 GND (power) hidden to GND, 12 (in), 13 (in), 14 VCC (power) hidden to VCC
part B pins: 4 (in), 6 (out), 7 GND (power) hidden to GND, 8 (in), 9 (in), 10 (in), 11 (in), 14 VCC (power) hidden to VCC
2 alternate drawings of the same symbol

## 74F377
designator U?
footprint DIP-20
pins: 1 ~{E} (in), 2 Q0 (out), 3 D0 (in), 4 D1 (in), 5 Q1 (out), 6 Q2 (out), 7 D2 (in), 8 D3 (in), 9 Q3 (out), 10 GND (power) hidden to GND, 11 CLK (in), 12 Q4 (out), 13 D4 (in), 14 D5 (in), 15 Q5 (out), 16 Q6 (out), 17 D6 (in), 18 D7 (in), 19 Q7 (out), 20 VCC (power) hidden to VCC
2 alternate drawings of the same symbol

## 74F381
designator U?
footprint DIP-20
pins: 1 A1 (in), 2 B1 (in), 3 A0 (in), 4 B0 (in), 5 S0 (in), 6 S1 (in), 7 S2 (in), 8 F0 (out), 9 F1 (out), 10 GND (power) hidden to GND, 11 F2 (out), 12 F3 (out), 13 ~{G} (out), 14 ~{P} (out), 15 CN (in), 16 B3 (in), 17 A3 (in), 18 B2 (in), 19 A2 (in), 20 VCC (power) hidden to VCC
2 alternate drawings of the same symbol

## 74F395
designator U?
footprint DIP-16
pins: 1 ~{MR} (in), 2 DS (in), 3 P0 (in), 4 P1 (in), 5 P2 (in), 6 P3 (in), 7 S (in), 8 GND (power) hidden to GND, 9 ~{OE} (in), 10 CLK (in), 11 Q3 (hiz), 12 O3 (hiz), 13 O2 (hiz), 14 O1 (hiz), 15 O0 (hiz), 16 VCC (power) hidden to VCC
2 alternate drawings of the same symbol

## 74F573
designator U?
footprint DIP-20
pins: 1 ~{OC} (in), 2 1D (in), 3 2D (in), 4 3D (in), 5 4D (in), 6 5D (in), 7 6D (in), 8 7D (in), 9 8D (in), 10 GND (power) hidden to GND, 11 C (in), 12 8Q (out), 13 7Q (out), 14 6Q (out), 15 5Q (out), 16 4Q (out), 17 3Q (out), 18 2Q (out), 19 1Q (out), 20 VCC (power) hidden to VCC
2 alternate drawings of the same symbol

## 74F574
designator U?
footprint DIP-20
pins: 1 ~{OC} (in), 2 1D (in), 3 2D (in), 4 3D (in), 5 4D (in), 6 5D (in), 7 6D (in), 8 7D (in), 9 8D (in), 10 GND (power) hidden to GND, 11 CLK (in), 12 8Q (out), 13 7Q (out), 14 6Q (out), 15 5Q (out), 16 4Q (out), 17 3Q (out), 18 2Q (out), 19 1Q (out), 20 VCC (power) hidden to VCC
2 alternate drawings of the same symbol

## 74HC42
designator U?
footprint DIP-16
pins: 1 ~{0} (out), 2 ~{1} (out), 3 ~{2} (out), 4 ~{3} (out), 5 ~{4} (out), 6 ~{5} (out), 7 ~{6} (out), 8 GND (power) hidden to GND, 9 ~{7} (out), 10 ~{8} (out), 11 ~{9} (out), 12 A3 (in), 13 A2 (in), 14 A1 (in), 15 A0 (in), 16 VCC (power) hidden to VCC
2 alternate drawings of the same symbol

## 74HC75
designator U?
footprint DIP-16
pins: 1 ~{Q0} (out), 2 D0 (in), 3 D1 (in), 4 E23 (in), 5 VCC (power) hidden to VCC, 6 D2 (in), 7 D3 (in), 8 ~{Q3} (out), 9 Q3 (out), 10 Q2 (out), 11 ~{Q2} (out), 12 GND (power) hidden to GND, 13 E01 (in), 14 ~{Q1} (out), 15 Q1 (out), 16 Q0 (out)
2 alternate drawings of the same symbol

## 74HC92
designator U?
footprint DIP-14
pins: 1 CLK1 (in), 5 VCC (power) hidden to VCC, 6 MR1 (in), 7 MR2 (in), 8 Q3 (out), 9 Q2 (out), 10 GND (power) hidden to GND, 11 Q1 (out), 12 Q0 (out), 14 CLK0 (in)
2 alternate drawings of the same symbol

## 74HC93
designator U?
footprint DIP-14
pins: 1 CLK1 (in), 2 MR1 (in), 3 MR2 (in), 5 VCC (power) hidden to VCC, 8 Q2 (out), 9 Q1 (out), 10 GND (power) hidden to GND, 11 Q3 (out), 12 Q0 (out), 14 CLK0 (in)
2 alternate drawings of the same symbol

## 74HC151
designator U?
footprint DIP-16
pins: 1 I3 (in), 2 I2 (in), 3 I1 (in), 4 I0 (in), 5 Z (out), 6 ~{Z} (out), 7 ~{E} (in), 8 GND (power) hidden to GND, 9 C (in), 10 B (in), 11 A (in), 12 I7 (in), 13 I6 (in), 14 I5 (in), 15 I4 (in), 16 VCC (power) hidden to VCC
2 alternate drawings of the same symbol

## 74HC164
designator U?
footprint DIP-14
pins: 1 A (in), 2 B (in), 3 Q0 (out), 4 Q1 (out), 5 Q2 (out), 6 Q3 (out), 7 GND (power) hidden to GND, 8 CLK (in), 9 ~{MR} (in), 10 Q4 (out), 11 Q5 (out), 12 Q6 (out), 13 Q7 (out), 14 VCC (power) hidden to VCC
2 alternate drawings of the same symbol

## 74HC180
designator U?
footprint DIP-14
pins: 1 G (in), 2 H (in), 3 EVEN (in), 4 ODD (in), 5 EVEN (in), 6 ODD (in), 7 GND (power) hidden to GND, 8 A (in), 9 B (in), 10 C (in), 11 D (in), 12 E (in), 13 F (in), 14 VCC (power) hidden to VCC
2 alternate drawings of the same symbol

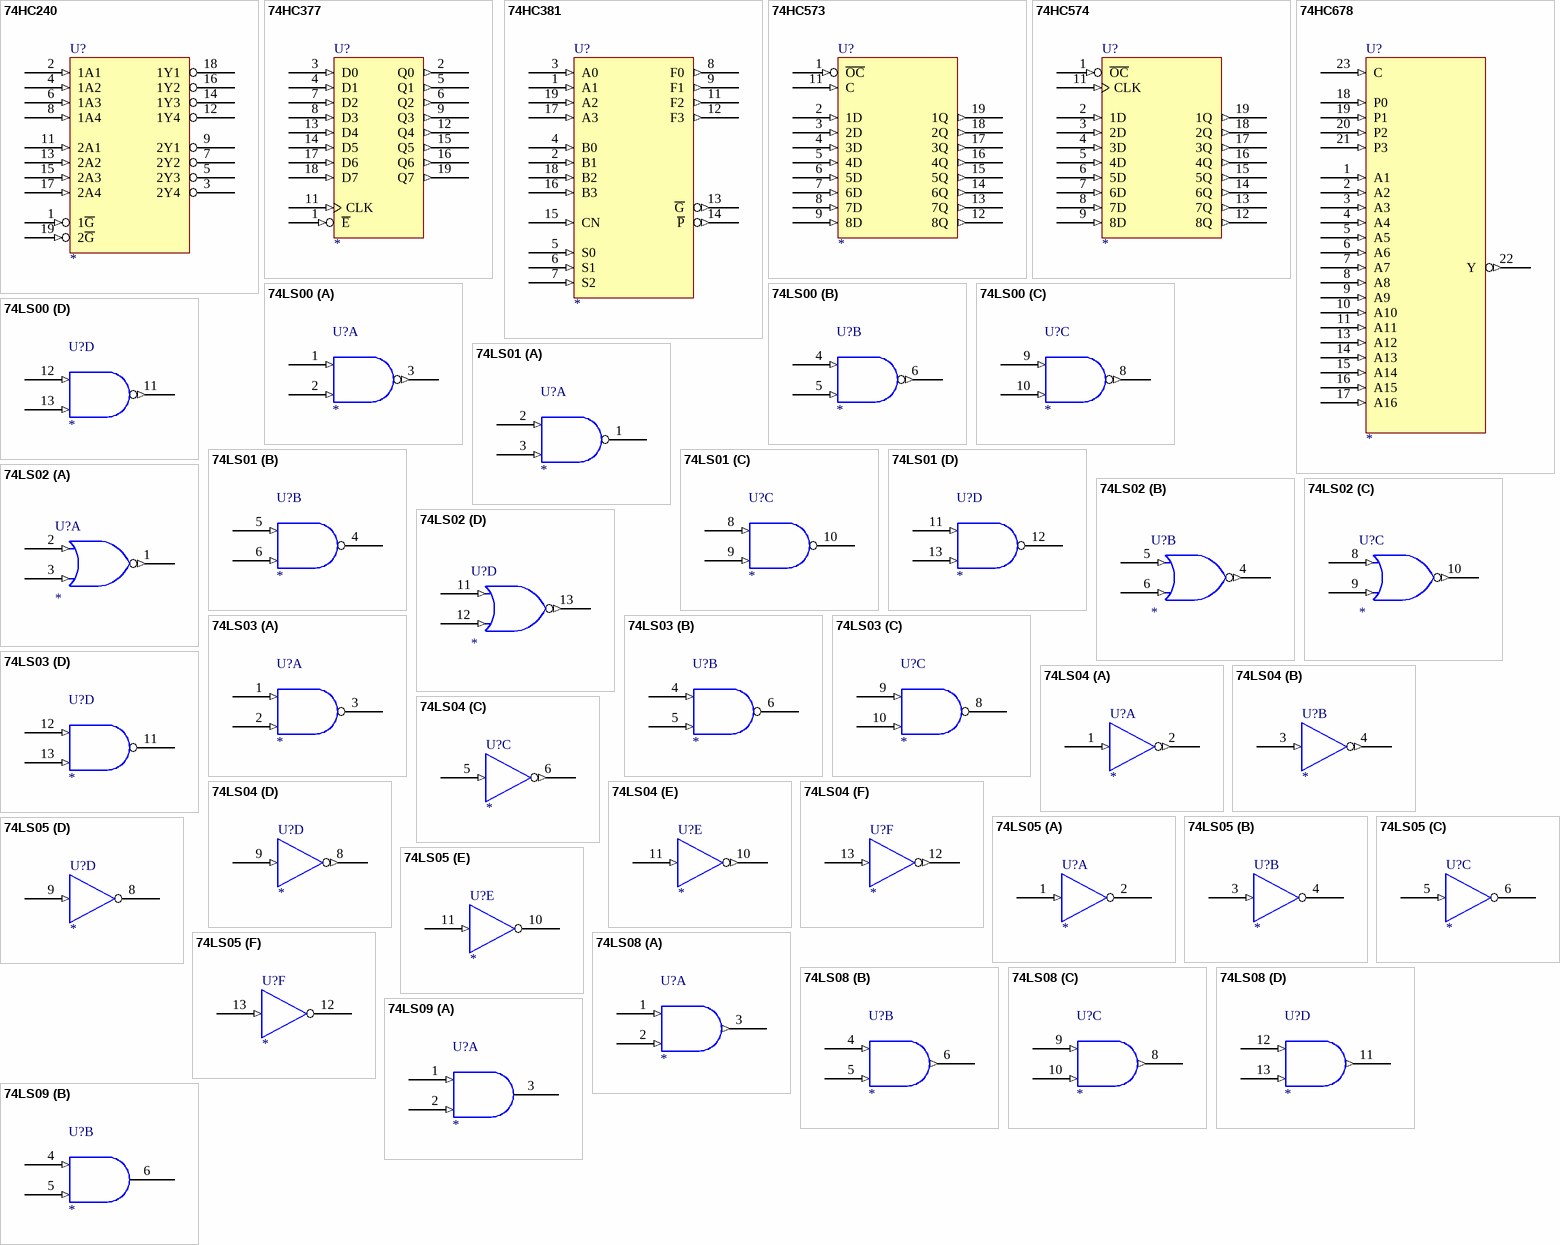
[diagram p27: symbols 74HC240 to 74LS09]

## 74HC240
designator U?
footprint DIP-20
pins: 1 1~{G} (in), 2 1A1 (in), 3 2Y4 (hiz), 4 1A2 (in), 5 2Y3 (hiz), 6 1A3 (in), 7 2Y2 (hiz), 8 1A4 (in), 9 2Y1 (hiz), 10 GND (power) hidden to GND, 11 2A1 (in), 12 1Y4 (hiz), 13 2A2 (in), 14 1Y3 (hiz), 15 2A3 (in), 16 1Y2 (hiz), 17 2A4 (in), 18 1Y1 (hiz), 19 2~{G} (in), 20 VCC (power) hidden to VCC
2 alternate drawings of the same symbol

## 74HC377
designator U?
footprint DIP-20
pins: 1 ~{E} (in), 2 Q0 (out), 3 D0 (in), 4 D1 (in), 5 Q1 (out), 6 Q2 (out), 7 D2 (in), 8 D3 (in), 9 Q3 (out), 11 CLK (in), 11 GND (power) hidden to GND, 12 Q4 (out), 13 D4 (in), 14 D5 (in), 15 Q5 (out), 16 Q6 (out), 17 D6 (in), 18 D7 (in), 19 Q7 (out), 20 VCC (power) hidden to VCC
2 alternate drawings of the same symbol

## 74HC381
designator U?
footprint DIP-20
pins: 1 A1 (in), 2 B1 (in), 3 A0 (in), 4 B0 (in), 5 S0 (in), 6 S1 (in), 7 S2 (in), 8 F0 (out), 9 F1 (out), 10 GND (power) hidden to GND, 11 F2 (out), 12 F3 (out), 13 ~{G} (out), 14 ~{P} (out), 15 CN (in), 16 B3 (in), 17 A3 (in), 18 B2 (in), 19 A2 (in), 20 VCC (power) hidden to VCC
2 alternate drawings of the same symbol

## 74HC573
designator U?
footprint DIP-20
pins: 1 ~{OC} (in), 2 1D (in), 3 2D (in), 4 3D (in), 5 4D (in), 6 5D (in), 7 6D (in), 8 7D (in), 9 8D (in), 10 GND (power) hidden to GND, 11 C (in), 12 8Q (out), 13 7Q (out), 14 6Q (out), 15 5Q (out), 16 4Q (out), 17 3Q (out), 18 2Q (out), 19 1Q (out), 20 VCC (power) hidden to VCC
2 alternate drawings of the same symbol

## 74HC574
designator U?
footprint DIP-20
pins: 1 ~{OC} (in), 2 1D (in), 3 2D (in), 4 3D (in), 5 4D (in), 6 5D (in), 7 6D (in), 8 7D (in), 9 8D (in), 10 GND (power) hidden to GND, 11 CLK (in), 12 8Q (out), 13 7Q (out), 14 6Q (out), 15 5Q (out), 16 4Q (out), 17 3Q (out), 18 2Q (out), 19 1Q (out), 20 VCC (power) hidden to VCC
2 alternate drawings of the same symbol

## 74HC678
designator U?
footprint DIP-24
pins: 1 A1 (in), 2 A2 (in), 3 A3 (in), 4 A4 (in), 5 A5 (in), 6 A6 (in), 7 A7 (in), 8 A8 (in), 9 A9 (in), 10 A10 (in), 11 A11 (in), 12 GND (power) hidden to GND, 13 A12 (in), 14 A13 (in), 15 A14 (in), 16 A15 (in), 17 A16 (in), 18 P0 (in), 19 P1 (in), 20 P2 (in), 21 P3 (in), 22 Y (out), 23 C (in), 24 VCC (power) hidden to VCC
2 alternate drawings of the same symbol

## 74LS00
designator U?
footprint DIP-14
part A pins: 1 (in), 2 (in), 3 (out), 7 GND (power) hidden to GND, 14 VCC (power) hidden to VCC
part B pins: 4 (in), 5 (in), 6 (out), 7 GND (power) hidden to GND, 14 VCC (power) hidden to VCC
part C pins: 7 GND (power) hidden to GND, 8 (out), 9 (in), 10 (in), 14 VCC (power) hidden to VCC
part D pins: 7 GND (power) hidden to GND, 11 (out), 12 (in), 13 (in), 14 VCC (power) hidden to VCC
2 alternate drawings of the same symbol

## 74LS01
designator U?
footprint DIP-14
part A pins: 1 (oc), 2 (in), 3 (in), 7 GND (power) hidden to GND, 14 VCC (power) hidden to VCC
part B pins: 4 (oc), 5 (in), 6 (in), 7 GND (power) hidden to GND, 14 VCC (power) hidden to VCC
part C pins: 7 GND (power) hidden to GND, 8 (in), 9 (in), 10 (oc), 14 VCC (power) hidden to VCC
part D pins: 7 GND (power) hidden to GND, 11 (in), 12 (oc), 13 (in), 14 VCC (power) hidden to VCC
2 alternate drawings of the same symbol

## 74LS02
designator U?
footprint DIP-14
part A pins: 1 (out), 2 (in), 3 (in), 7 GND (power) hidden to GND, 14 VCC (power) hidden to VCC
part B pins: 4 (out), 5 (in), 6 (in), 7 GND (power) hidden to GND, 14 VCC (power) hidden to VCC
part C pins: 7 GND (power) hidden to GND, 8 (in), 9 (in), 10 (out), 14 VCC (power) hidden to VCC
part D pins: 7 GND (power) hidden to GND, 11 (in), 12 (in), 13 (out), 14 VCC (power) hidden to VCC
2 alternate drawings of the same symbol

## 74LS03
designator U?
footprint DIP-14
part A pins: 1 (in), 2 (in), 3 (oc), 7 GND (power) hidden to GND, 14 VCC (power) hidden to VCC
part B pins: 4 (in), 5 (in), 6 (oc), 7 GND (power) hidden to GND, 14 VCC (power) hidden to VCC
part C pins: 7 GND (power) hidden to GND, 8 (oc), 9 (in), 10 (in), 14 VCC (power) hidden to VCC
part D pins: 7 GND (power) hidden to GND, 11 (oc), 12 (in), 13 (in), 14 VCC (power) hidden to VCC
2 alternate drawings of the same symbol

## 74LS04
designator U?
footprint DIP-14
part A pins: 1 (in), 2 (out), 7 GND (power) hidden to GND, 14 VCC (power) hidden to VCC
part B pins: 3 (in), 4 (out), 7 GND (power) hidden to GND, 14 VCC (power) hidden to VCC
part C pins: 5 (in), 6 (out), 7 GND (power) hidden to GND, 14 VCC (power) hidden to VCC
part D pins: 7 GND (power) hidden to GND, 8 (out), 9 (in), 14 VCC (power) hidden to VCC
part E pins: 7 GND (power) hidden to GND, 10 (out), 11 (in), 14 VCC (power) hidden to VCC
part F pins: 7 GND (power) hidden to GND, 12 (out), 13 (in), 14 VCC (power) hidden to VCC
2 alternate drawings of the same symbol

## 74LS05
designator U?
footprint DIP-14
part A pins: 1 (in), 2 (oc), 7 GND (power) hidden to GND, 14 VCC (power) hidden to VCC
part B pins: 3 (in), 4 (oc), 7 GND (power) hidden to GND, 14 VCC (power) hidden to VCC
part C pins: 5 (in), 6 (oc), 7 GND (power) hidden to GND, 14 VCC (power) hidden to VCC
part D pins: 7 GND (power) hidden to GND, 8 (oc), 9 (in), 14 VCC (power) hidden to VCC
part E pins: 7 GND (power) hidden to GND, 10 (oc), 11 (in), 14 VCC (power) hidden to VCC
part F pins: 7 GND (power) hidden to GND, 12 (oc), 13 (in), 14 VCC (power) hidden to VCC
2 alternate drawings of the same symbol

## 74LS08
designator U?
footprint DIP-14
part A pins: 1 (in), 2 (in), 3 (out), 7 GND (power) hidden to GND, 14 VCC (power) hidden to VCC
part B pins: 4 (in), 5 (in), 6 (out), 7 GND (power) hidden to GND, 14 VCC (power) hidden to VCC
part C pins: 7 GND (power) hidden to GND, 8 (out), 9 (in), 10 (in), 14 VCC (power) hidden to VCC
part D pins: 7 GND (power) hidden to GND, 11 (out), 12 (in), 13 (in), 14 VCC (power) hidden to VCC
2 alternate drawings of the same symbol

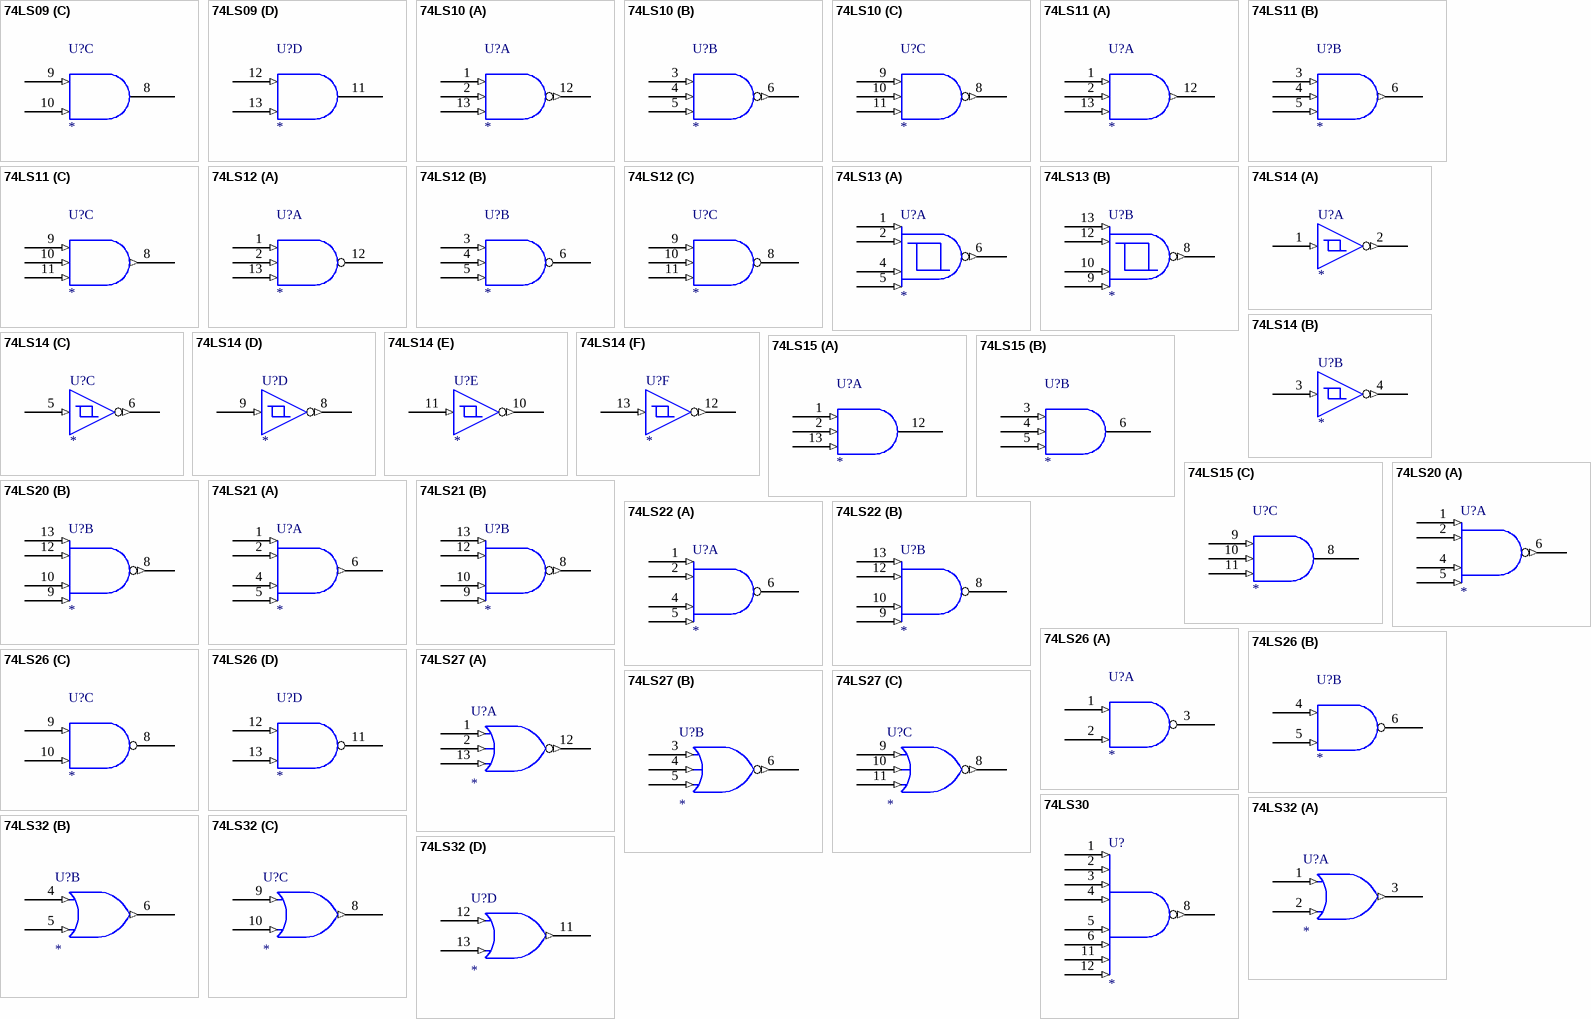
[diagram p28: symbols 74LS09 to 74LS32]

## 74LS09
designator U?
footprint DIP-14
part A pins: 1 (in), 2 (in), 3 (oc), 7 GND (power) hidden to GND, 14 VCC (power) hidden to VCC
part B pins: 4 (in), 5 (in), 6 (oc), 7 GND (power) hidden to GND, 14 VCC (power) hidden to VCC
part C pins: 7 GND (power) hidden to GND, 8 (oc), 9 (in), 10 (in), 14 VCC (power) hidden to VCC
part D pins: 7 GND (power) hidden to GND, 11 (oc), 12 (in), 13 (in), 14 VCC (power) hidden to VCC
2 alternate drawings of the same symbol

## 74LS10
designator U?
footprint DIP-14
part A pins: 1 (in), 2 (in), 7 GND (power) hidden to GND, 12 (out), 13 (in), 14 VCC (power) hidden to VCC
part B pins: 3 (in), 4 (in), 5 (in), 6 (out), 7 GND (power) hidden to GND, 14 VCC (power) hidden to VCC
part C pins: 7 GND (power) hidden to GND, 8 (out), 9 (in), 10 (in), 11 (in), 14 VCC (power) hidden to VCC
2 alternate drawings of the same symbol

## 74LS11
designator U?
footprint DIP-14
part A pins: 1 (in), 2 (in), 7 GND (power) hidden to GND, 12 (out), 13 (in), 14 VCC (power) hidden to VCC
part B pins: 3 (in), 4 (in), 5 (in), 6 (out), 7 GND (power) hidden to GND, 14 VCC (power) hidden to VCC
part C pins: 7 GND (power) hidden to GND, 8 (out), 9 (in), 10 (in), 11 (in), 14 VCC (power) hidden to VCC
2 alternate drawings of the same symbol

## 74LS12
designator U?
footprint DIP-14
part A pins: 1 (in), 2 (in), 7 GND (power) hidden to GND, 12 (oc), 13 (in), 14 VCC (power) hidden to VCC
part B pins: 3 (in), 4 (in), 5 (in), 6 (oc), 7 GND (power) hidden to GND, 14 VCC (power) hidden to VCC
part C pins: 7 GND (power) hidden to GND, 8 (oc), 9 (in), 10 (in), 11 (in), 14 VCC (power) hidden to VCC
2 alternate drawings of the same symbol

## 74LS13
designator U?
footprint DIP-14
part A pins: 1 (in), 2 (in), 4 (in), 5 (in), 6 (out), 7 GND (power) hidden to GND, 14 VCC (power) hidden to VCC
part B pins: 7 GND (power) hidden to GND, 8 (out), 9 (in), 10 (in), 12 (in), 13 (in), 14 VCC (power) hidden to VCC
2 alternate drawings of the same symbol

## 74LS14
designator U?
footprint DIP14E
footprint DIP-14
part A pins: 1 (in), 2 (out), 7 GND (power) hidden to GND, 14 VCC (power) hidden to VCC
part B pins: 3 (in), 4 (out), 7 GND (power) hidden to GND, 14 VCC (power) hidden to VCC
part C pins: 5 (in), 6 (out), 7 GND (power) hidden to GND, 14 VCC (power) hidden to VCC
part D pins: 7 GND (power) hidden to GND, 8 (out), 9 (in), 14 VCC (power) hidden to VCC
part E pins: 7 GND (power) hidden to GND, 10 (out), 11 (in), 14 VCC (power) hidden to VCC
part F pins: 7 GND (power) hidden to GND, 12 (out), 13 (in), 14 VCC (power) hidden to VCC
2 alternate drawings of the same symbol

## 74LS15
designator U?
footprint DIP-14
part A pins: 1 (in), 2 (in), 7 GND (power) hidden to GND, 12 (oc), 13 (in), 14 VCC (power) hidden to VCC
part B pins: 3 (in), 4 (in), 5 (in), 6 (oc), 7 GND (power) hidden to GND, 14 VCC (power) hidden to VCC
part C pins: 7 GND (power) hidden to GND, 8 (oc), 9 (in), 10 (in), 11 (in), 14 VCC (power) hidden to VCC
2 alternate drawings of the same symbol

## 74LS20
designator U?
footprint DIP-14
part A pins: 1 (in), 2 (in), 4 (in), 5 (in), 6 (out), 7 GND (power) hidden to GND, 14 VCC (power) hidden to VCC
part B pins: 7 GND (power) hidden to GND, 8 (out), 9 (in), 10 (in), 12 (in), 13 (in), 14 VCC (power) hidden to VCC
2 alternate drawings of the same symbol

## 74LS21
designator U?
footprint DIP-14
part A pins: 1 (in), 2 (in), 4 (in), 5 (in), 6 (out), 7 GND (power) hidden to GND, 14 VCC (power) hidden to VCC
part B pins: 7 GND (power) hidden to GND, 8 (out), 9 (in), 10 (in), 12 (in), 13 (in), 14 VCC (power) hidden to VCC
2 alternate drawings of the same symbol

## 74LS22
designator U?
footprint DIP-14
part A pins: 1 (in), 2 (in), 4 (in), 5 (in), 6 (oc), 7 GND (power) hidden to GND, 14 VCC (power) hidden to VCC
part B pins: 7 GND (power) hidden to GND, 8 (oc), 9 (in), 10 (in), 12 (in), 13 (in), 14 VCC (power) hidden to VCC
2 alternate drawings of the same symbol

## 74LS26
designator U?
footprint DIP-14
part A pins: 1 (in), 2 (in), 3 (oc), 7 GND (power) hidden to GND, 14 VCC (power) hidden to VCC
part B pins: 4 (in), 5 (in), 6 (oc), 7 GND (power) hidden to GND, 14 VCC (power) hidden to VCC
part C pins: 7 GND (power) hidden to GND, 8 (oc), 9 (in), 10 (in), 14 VCC (power) hidden to VCC
part D pins: 7 GND (power) hidden to GND, 11 (oc), 12 (in), 13 (in), 14 VCC (power) hidden to VCC
2 alternate drawings of the same symbol

## 74LS27
designator U?
footprint DIP-14
part A pins: 1 (in), 2 (in), 7 GND (power) hidden to GND, 12 (out), 13 (in), 14 VCC (power) hidden to VCC
part B pins: 3 (in), 4 (in), 5 (in), 6 (out), 7 GND (power) hidden to GND, 14 VCC (power) hidden to VCC
part C pins: 7 GND (power) hidden to GND, 8 (out), 9 (in), 10 (in), 11 (in), 14 VCC (power) hidden to VCC
2 alternate drawings of the same symbol

## 74LS30
designator U?
footprint DIP-14
pins: 1 (in), 2 (in), 3 (in), 4 (in), 5 (in), 6 (in), 7 GND (power) hidden to GND, 8 (out), 11 (in), 12 (in), 14 VCC (power) hidden to VCC
2 alternate drawings of the same symbol

## 74LS32
designator U?
footprint DIP-14
part A pins: 1 (in), 2 (in), 3 (out), 7 GND (power) hidden to GND, 14 VCC (power) hidden to VCC
part B pins: 4 (in), 5 (in), 6 (out), 7 GND (power) hidden to GND, 14 VCC (power) hidden to VCC
part C pins: 7 GND (power) hidden to GND, 8 (out), 9 (in), 10 (in), 14 VCC (power) hidden to VCC
part D pins: 7 GND (power) hidden to GND, 11 (out), 12 (in), 13 (in), 14 VCC (power) hidden to VCC
2 alternate drawings of the same symbol

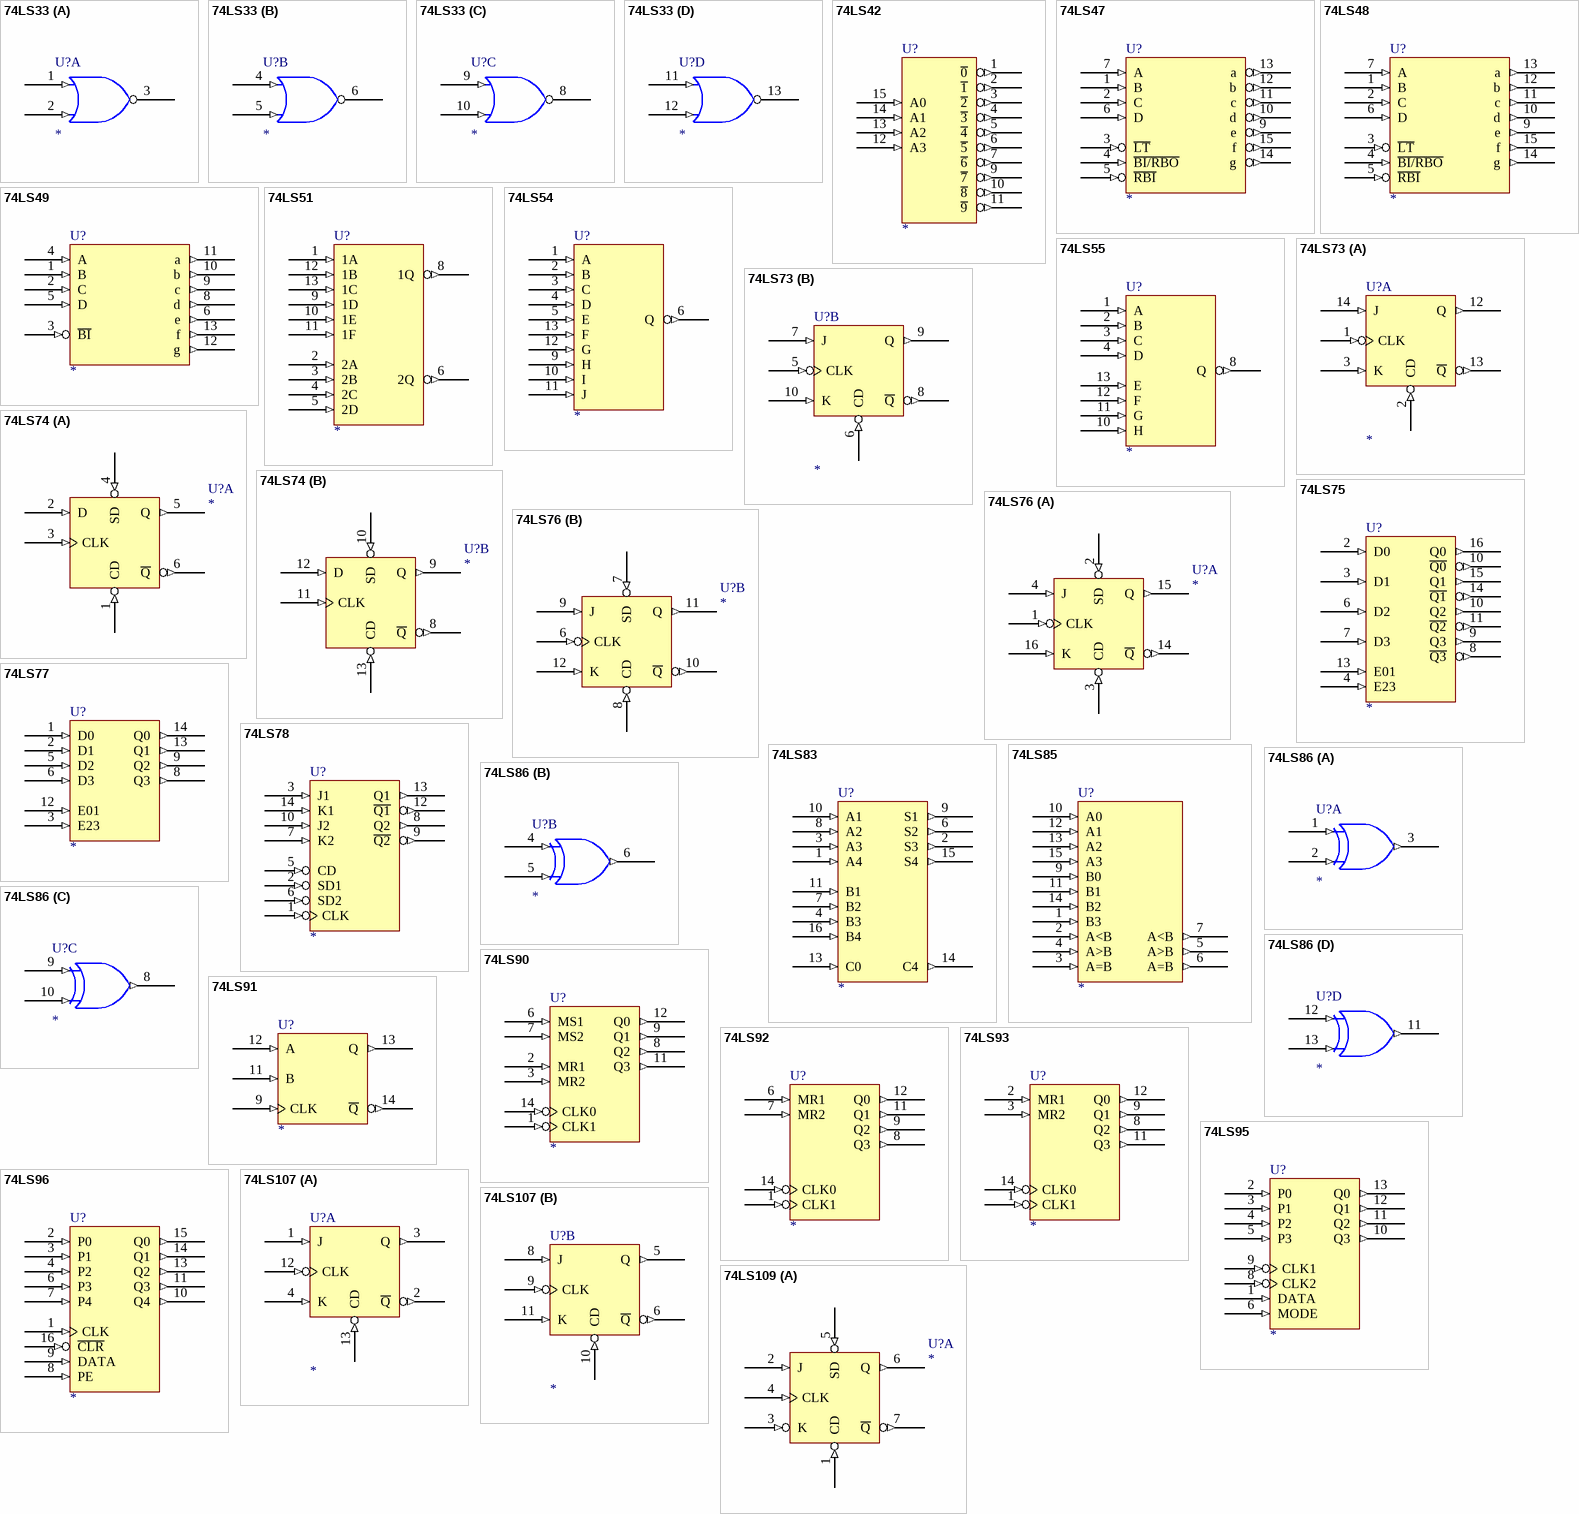
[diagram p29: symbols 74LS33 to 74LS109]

## 74LS33
designator U?
footprint DIP-14
part A pins: 1 (in), 2 (in), 3 (oc), 7 GND (power) hidden to GND, 14 VCC (power) hidden to VCC
part B pins: 4 (in), 5 (in), 6 (oc), 7 GND (power) hidden to GND, 14 VCC (power) hidden to VCC
part C pins: 7 GND (power) hidden to GND, 8 (oc), 9 (in), 10 (in), 14 VCC (power) hidden to VCC
part D pins: 7 GND (power) hidden to GND, 11 (in), 12 (in), 13 (oc), 14 VCC (power) hidden to VCC
2 alternate drawings of the same symbol

## 74LS42
designator U?
footprint DIP-14
pins: 1 ~{0} (out), 2 ~{1} (out), 3 ~{2} (out), 4 ~{3} (out), 5 ~{4} (out), 6 ~{5} (out), 7 ~{6} (out), 8 GND (power) hidden to GND, 9 ~{7} (out), 10 ~{8} (out), 11 ~{9} (out), 12 A3 (in), 13 A2 (in), 14 A1 (in), 15 A0 (in), 16 VCC (power) hidden to VCC
2 alternate drawings of the same symbol

## 74LS47
designator U?
footprint DIP-14
pins: 1 B (in), 2 C (in), 3 ~{LT} (in), 4 ~{BI/RBO} (in), 5 ~{RBI} (in), 6 D (in), 7 A (in), 8 GND (power) hidden to GND, 9 e (out), 10 d (out), 11 c (out), 12 b (out), 13 a (out), 14 g (out), 15 f (out), 16 VCC (power) hidden to VCC
2 alternate drawings of the same symbol

## 74LS48
designator U?
footprint DIP-14
pins: 1 B (in), 2 C (in), 3 ~{LT} (in), 4 ~{BI/RBO} (in), 5 ~{RBI} (in), 6 D (in), 7 A (in), 8 GND (power) hidden to GND, 9 e (out), 10 d (out), 11 c (out), 12 b (out), 13 a (out), 14 g (out), 15 f (out), 16 VCC (power) hidden to VCC
2 alternate drawings of the same symbol

## 74LS49
designator U?
footprint DIP-14
pins: 1 B (in), 2 C (in), 3 ~{BI} (in), 4 A (in), 5 D (in), 6 e (out), 7 GND (power) hidden to GND, 8 d (out), 9 c (out), 10 b (out), 11 a (out), 12 g (out), 13 f (out), 14 VCC (power) hidden to VCC
2 alternate drawings of the same symbol

## 74LS51
designator U?
footprint DIP-14
pins: 1 1A (in), 2 2A (in), 3 2B (in), 4 2C (in), 5 2D (in), 6 2Q (out), 7 GND (power) hidden to GND, 8 1Q (out), 9 1D (in), 10 1E (in), 11 1F (in), 12 1B (in), 13 1C (in), 14 VCC (power) hidden to VCC
2 alternate drawings of the same symbol

## 74LS54
designator U?
footprint DIP-14
pins: 1 A (in), 2 B (in), 3 C (in), 4 D (in), 5 E (in), 6 Q (out), 7 GND (power) hidden to GND, 9 H (in), 10 I (in), 11 J (in), 12 G (in), 13 F (in), 14 VCC (power) hidden to VCC
2 alternate drawings of the same symbol

## 74LS55
designator U?
footprint DIP-14
pins: 1 A (in), 2 B (in), 3 C (in), 4 D (in), 7 GND (power) hidden to GND, 8 Q (out), 10 H (in), 11 G (in), 12 F (in), 13 E (in), 14 VCC (power) hidden to VCC
2 alternate drawings of the same symbol

## 74LS73
designator U?
footprint DIP-14
part A pins: 1 CLK (in), 2 CD (in), 3 K (in), 4 VCC (power) hidden to VCC, 11 GND (power) hidden to GND, 12 Q (out), 13 ~{Q} (out), 14 J (in)
part B pins: 4 VCC (power) hidden to VCC, 5 CLK (in), 6 CD (in), 7 J (in), 8 ~{Q} (out), 9 Q (out), 10 K (in), 11 GND (power) hidden to GND
2 alternate drawings of the same symbol

## 74LS74
designator U?
footprint DIP-14
part A pins: 1 CD (in), 2 D (in), 3 CLK (in), 4 SD (in), 5 Q (out), 6 ~{Q} (out), 7 GND (power) hidden to GND, 14 VCC (power) hidden to VCC
part B pins: 7 GND (power) hidden to GND, 8 ~{Q} (out), 9 Q (out), 10 SD (in), 11 CLK (in), 12 D (in), 13 CD (in), 14 VCC (power) hidden to VCC
2 alternate drawings of the same symbol

## 74LS75
designator U?
footprint DIP-16
pins: 2 D0 (in), 3 D1 (in), 4 E23 (in), 5 VCC (power) hidden to VCC, 6 D2 (in), 7 D3 (in), 8 ~{Q3} (out), 9 Q3 (out), 10 Q2 (out), 10 ~{Q0} (out), 11 ~{Q2} (out), 12 GND (power) hidden to GND, 13 E01 (in), 14 ~{Q1} (out), 15 Q1 (out), 16 Q0 (out)
2 alternate drawings of the same symbol

## 74LS76
designator U?
footprint DIP-16
part A pins: 1 CLK (in), 2 SD (in), 3 CD (in), 4 J (in), 5 VCC (power) hidden to VCC, 13 GND (power) hidden to GND, 14 ~{Q} (out), 15 Q (out), 16 K (in)
part B pins: 5 VCC (power) hidden to VCC, 6 CLK (in), 7 SD (in), 8 CD (in), 9 J (in), 10 ~{Q} (out), 11 Q (out), 12 K (in), 13 GND (power) hidden to GND
2 alternate drawings of the same symbol

## 74LS77
designator U?
footprint DIP-14
pins: 1 D0 (in), 2 D1 (in), 3 E23 (in), 4 VCC (power) hidden to VCC, 5 D2 (in), 6 D3 (in), 8 Q3 (out), 9 Q2 (out), 11 GND (power) hidden to GND, 12 E01 (in), 13 Q1 (out), 14 Q0 (out)
2 alternate drawings of the same symbol

## 74LS78
designator U?
footprint DIP-14
pins: 1 CLK (in), 2 SD1 (in), 3 J1 (in), 4 VCC (power) hidden to VCC, 5 CD (in), 6 SD2 (in), 7 K2 (in), 8 Q2 (out), 9 ~{Q2} (out), 10 J2 (in), 11 GND (power) hidden to GND, 12 ~{Q1} (out), 13 Q1 (out), 14 K1 (in)
2 alternate drawings of the same symbol

## 74LS83
designator U?
footprint DIP-16
pins: 1 A4 (in), 2 S3 (out), 3 A3 (in), 4 B3 (in), 5 VCC (power) hidden to VCC, 6 S2 (out), 7 B2 (in), 8 A2 (in), 9 S1 (out), 10 A1 (in), 11 B1 (in), 12 GND (power) hidden to GND, 13 C0 (in), 14 C4 (out), 15 S4 (out), 16 B4 (in)
2 alternate drawings of the same symbol

## 74LS85
designator U?
footprint DIP-16
pins: 1 B3 (in), 2 A<B (in), 3 A=B (in), 4 A>B (in), 5 A>B (out), 6 A=B (out), 7 A<B (out), 8 GND (power) hidden to GND, 9 B0 (in), 10 A0 (in), 11 B1 (in), 12 A1 (in), 13 A2 (in), 14 B2 (in), 15 A3 (in), 16 VCC (power) hidden to VCC
2 alternate drawings of the same symbol

## 74LS86
designator U?
footprint DIP-14
part A pins: 1 (in), 2 (in), 3 (out), 7 GND (power) hidden to GND, 14 VCC (power) hidden to VCC
part B pins: 4 (in), 5 (in), 6 (out), 7 GND (power) hidden to GND, 14 VCC (power) hidden to VCC
part C pins: 7 GND (power) hidden to GND, 8 (out), 9 (in), 10 (in), 14 VCC (power) hidden to VCC
part D pins: 7 GND (power) hidden to GND, 11 (out), 12 (in), 13 (in), 14 VCC (power) hidden to VCC
2 alternate drawings of the same symbol

## 74LS90
designator U?
footprint DIP-14
pins: 1 CLK1 (in), 2 MR1 (in), 3 MR2 (in), 5 VCC (power) hidden to VCC, 6 MS1 (in), 7 MS2 (in), 8 Q2 (out), 9 Q1 (out), 10 GND (power) hidden to GND, 11 Q3 (out), 12 Q0 (out), 14 CLK0 (in)
2 alternate drawings of the same symbol

## 74LS91
designator U?
footprint DIP-14
pins: 5 VCC (power) hidden to VCC, 9 CLK (in), 11 B (in), 11 GND (power) hidden to GND, 12 A (in), 13 Q (out), 14 ~{Q} (out)
2 alternate drawings of the same symbol

## 74LS92
designator U?
footprint DIP-14
pins: 1 CLK1 (in), 5 VCC (power) hidden to VCC, 6 MR1 (in), 7 MR2 (in), 8 Q3 (out), 9 Q2 (out), 11 Q1 (out), 11 GND (power) hidden to GND, 12 Q0 (out), 14 CLK0 (in)
2 alternate drawings of the same symbol

## 74LS93
designator U?
footprint DIP-14
pins: 1 CLK1 (in), 2 MR1 (in), 3 MR2 (in), 5 VCC (power) hidden to VCC, 8 Q2 (out), 9 Q1 (out), 11 Q3 (out), 11 GND (power) hidden to GND, 12 Q0 (out), 14 CLK0 (in)
2 alternate drawings of the same symbol

## 74LS95
designator U?
footprint DIP-14
pins: 1 DATA (in), 2 P0 (in), 3 P1 (in), 4 P2 (in), 5 P3 (in), 6 MODE (in), 8 CLK2 (in), 8 GND (power) hidden to GND, 9 CLK1 (in), 10 Q3 (out), 11 Q2 (out), 12 Q1 (out), 13 Q0 (out), 16 VCC (power) hidden to VCC
2 alternate drawings of the same symbol

## 74LS96
designator U?
footprint DIP-16
pins: 1 CLK (in), 2 P0 (in), 3 P1 (in), 4 P2 (in), 5 VCC (power) hidden to VCC, 6 P3 (in), 7 P4 (in), 8 PE (in), 9 DATA (in), 10 Q4 (out), 11 Q3 (out), 12 GND (power) hidden to GND, 13 Q2 (out), 14 Q1 (out), 15 Q0 (out), 16 ~{CLR} (in)
2 alternate drawings of the same symbol

## 74LS107
designator U?
footprint DIP-14
part A pins: 1 J (in), 2 ~{Q} (out), 3 Q (out), 4 K (in), 7 GND (power) hidden to GND, 12 CLK (in), 13 CD (in), 14 VCC (power) hidden to VCC
part B pins: 5 Q (out), 6 ~{Q} (out), 7 GND (power) hidden to GND, 8 J (in), 9 CLK (in), 10 CD (in), 11 K (in), 14 VCC (power) hidden to VCC
2 alternate drawings of the same symbol

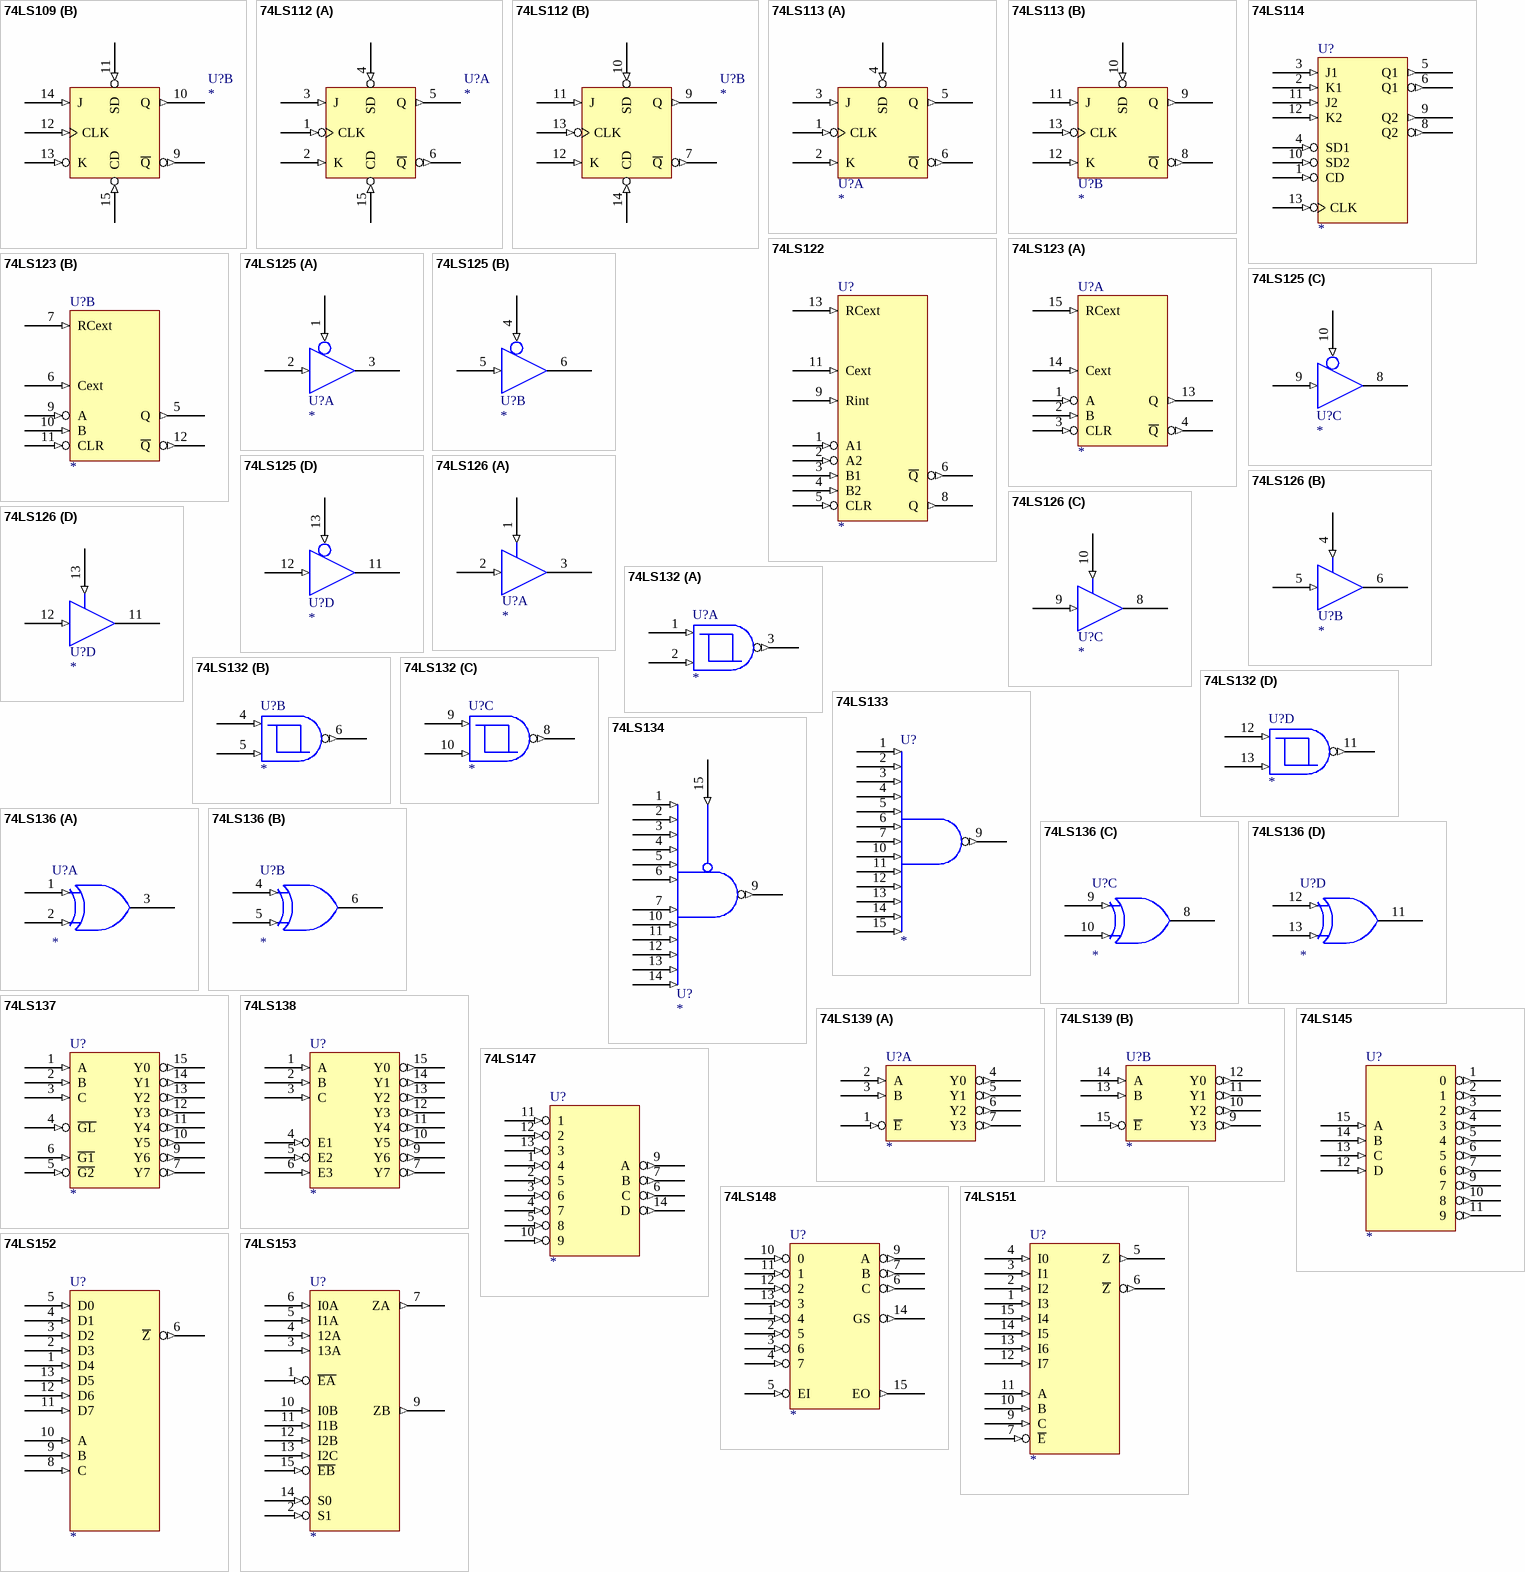
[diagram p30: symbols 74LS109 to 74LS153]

## 74LS109
designator U?
footprint DIP-16
part A pins: 1 CD (in), 2 J (in), 3 K (in), 4 CLK (in), 5 SD (in), 6 Q (out), 7 ~{Q} (out), 8 GND (power) hidden to GND, 16 VCC (power) hidden to VCC
part B pins: 8 GND (power) hidden to GND, 9 ~{Q} (out), 10 Q (out), 11 SD (in), 12 CLK (in), 13 K (in), 14 J (in), 15 CD (in), 16 VCC (power) hidden to VCC
2 alternate drawings of the same symbol

## 74LS112
designator U?
footprint DIP-16
part A pins: 1 CLK (in), 2 K (in), 3 J (in), 4 SD (in), 5 Q (out), 6 ~{Q} (out), 8 GND (power) hidden to GND, 15 CD (in), 16 VCC (power) hidden to VCC
part B pins: 7 ~{Q} (out), 8 GND (power) hidden to GND, 9 Q (out), 10 SD (in), 11 J (in), 12 K (in), 13 CLK (in), 14 CD (in), 16 VCC (power) hidden to VCC
2 alternate drawings of the same symbol

## 74LS113
designator U?
footprint DIP-14
part A pins: 1 CLK (in), 2 K (in), 3 J (in), 4 SD (in), 5 Q (out), 6 ~{Q} (out), 7 GND (power) hidden to GND, 14 VCC (power) hidden to VCC
part B pins: 7 GND (power) hidden to GND, 8 ~{Q} (out), 9 Q (out), 10 SD (in), 11 J (in), 12 K (in), 13 CLK (in), 14 VCC (power) hidden to VCC
2 alternate drawings of the same symbol

## 74LS114
designator U?
footprint DIP-14
pins: 1 CD (in), 2 K1 (in), 3 J1 (in), 4 SD1 (in), 5 Q1 (out), 6 Q1 (out), 7 GND (power) hidden to GND, 8 Q2 (out), 9 Q2 (out), 10 SD2 (in), 11 J2 (in), 12 K2 (in), 13 CLK (in), 14 VCC (power) hidden to VCC
2 alternate drawings of the same symbol

## 74LS122
designator U?
footprint DIP-14
pins: 1 A1 (in), 2 A2 (in), 3 B1 (in), 4 B2 (in), 5 CLR (in), 6 ~{Q} (out), 7 GND (power) hidden to GND, 8 Q (out), 9 Rint (in), 11 Cext (in), 13 RCext (in), 14 VCC (power) hidden to VCC
2 alternate drawings of the same symbol

## 74LS123
designator U?
footprint DIP-16
part A pins: 1 A (in), 2 B (in), 3 CLR (in), 4 ~{Q} (out), 8 GND (power) hidden to GND, 13 Q (out), 14 Cext (in), 15 RCext (in), 16 VCC (power) hidden to VCC
part B pins: 5 Q (out), 6 Cext (in), 7 RCext (in), 8 GND (power) hidden to GND, 9 A (in), 10 B (in), 11 CLR (in), 12 ~{Q} (out), 16 VCC (power) hidden to VCC
2 alternate drawings of the same symbol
